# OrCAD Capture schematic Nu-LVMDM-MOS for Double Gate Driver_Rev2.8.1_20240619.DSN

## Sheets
1 Driver Board: size A3; title: Driver Board; rev: V1.0
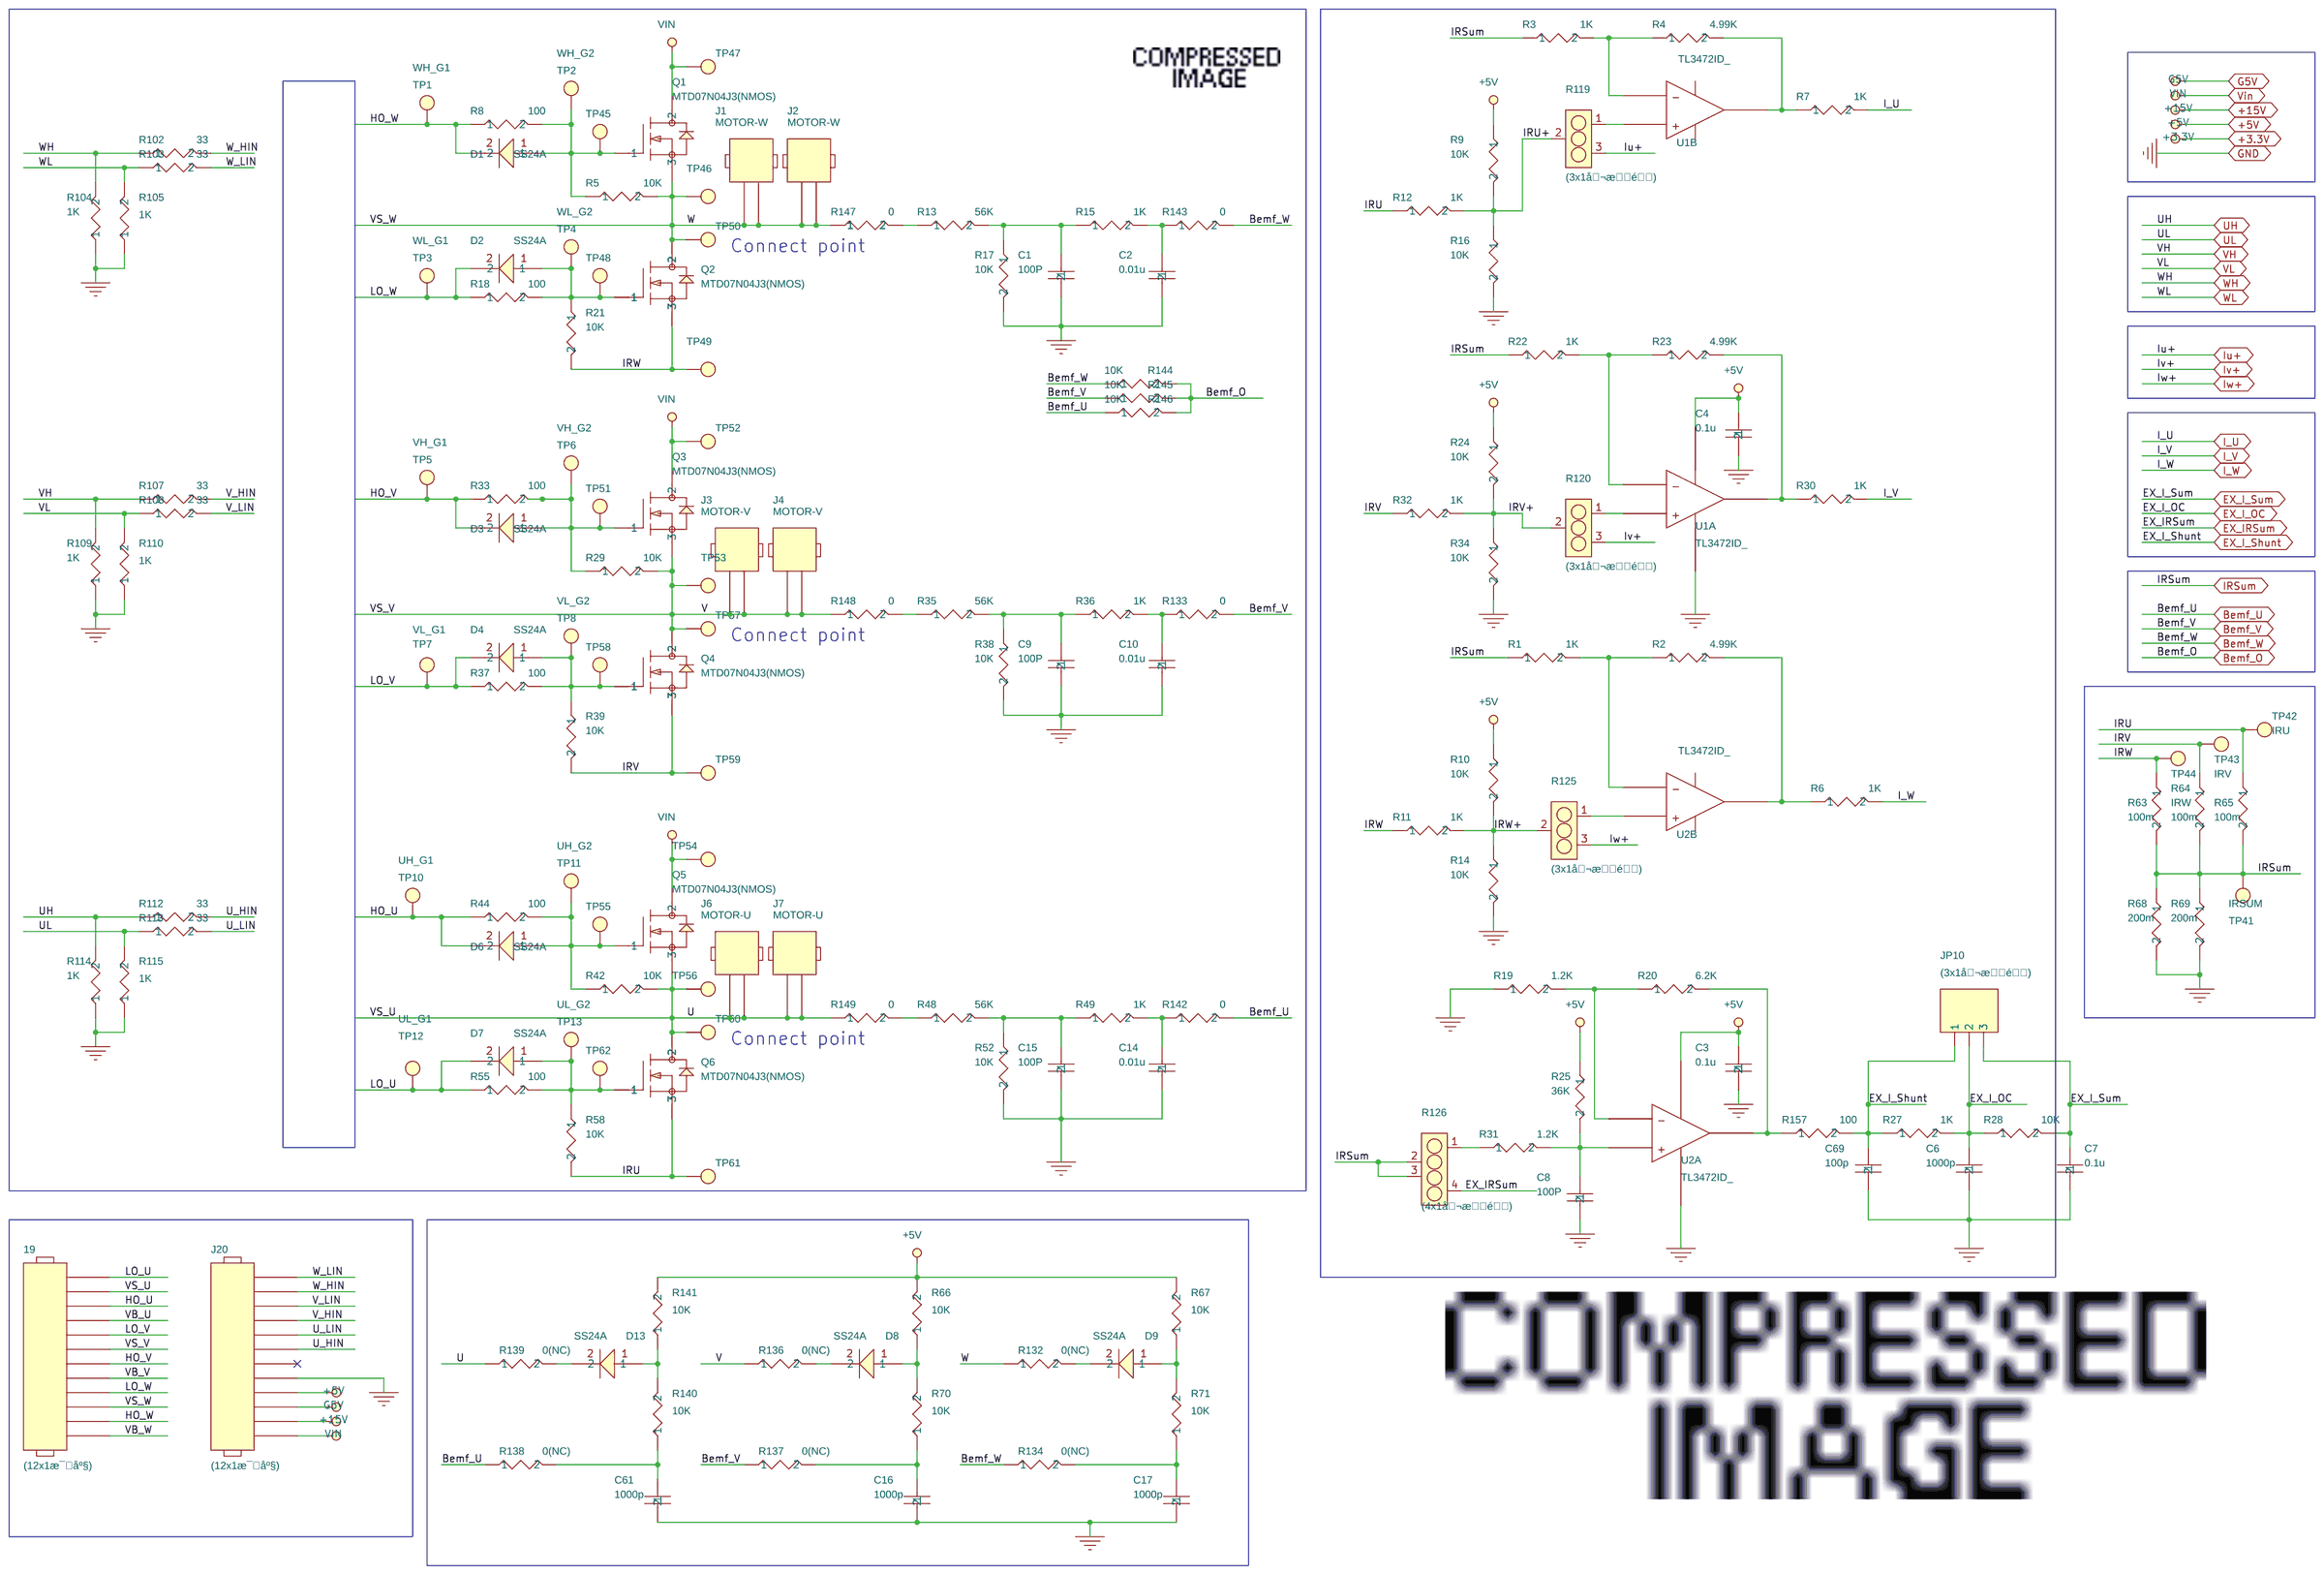
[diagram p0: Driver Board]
2 Power: size A4; title: Power; rev: 1.0
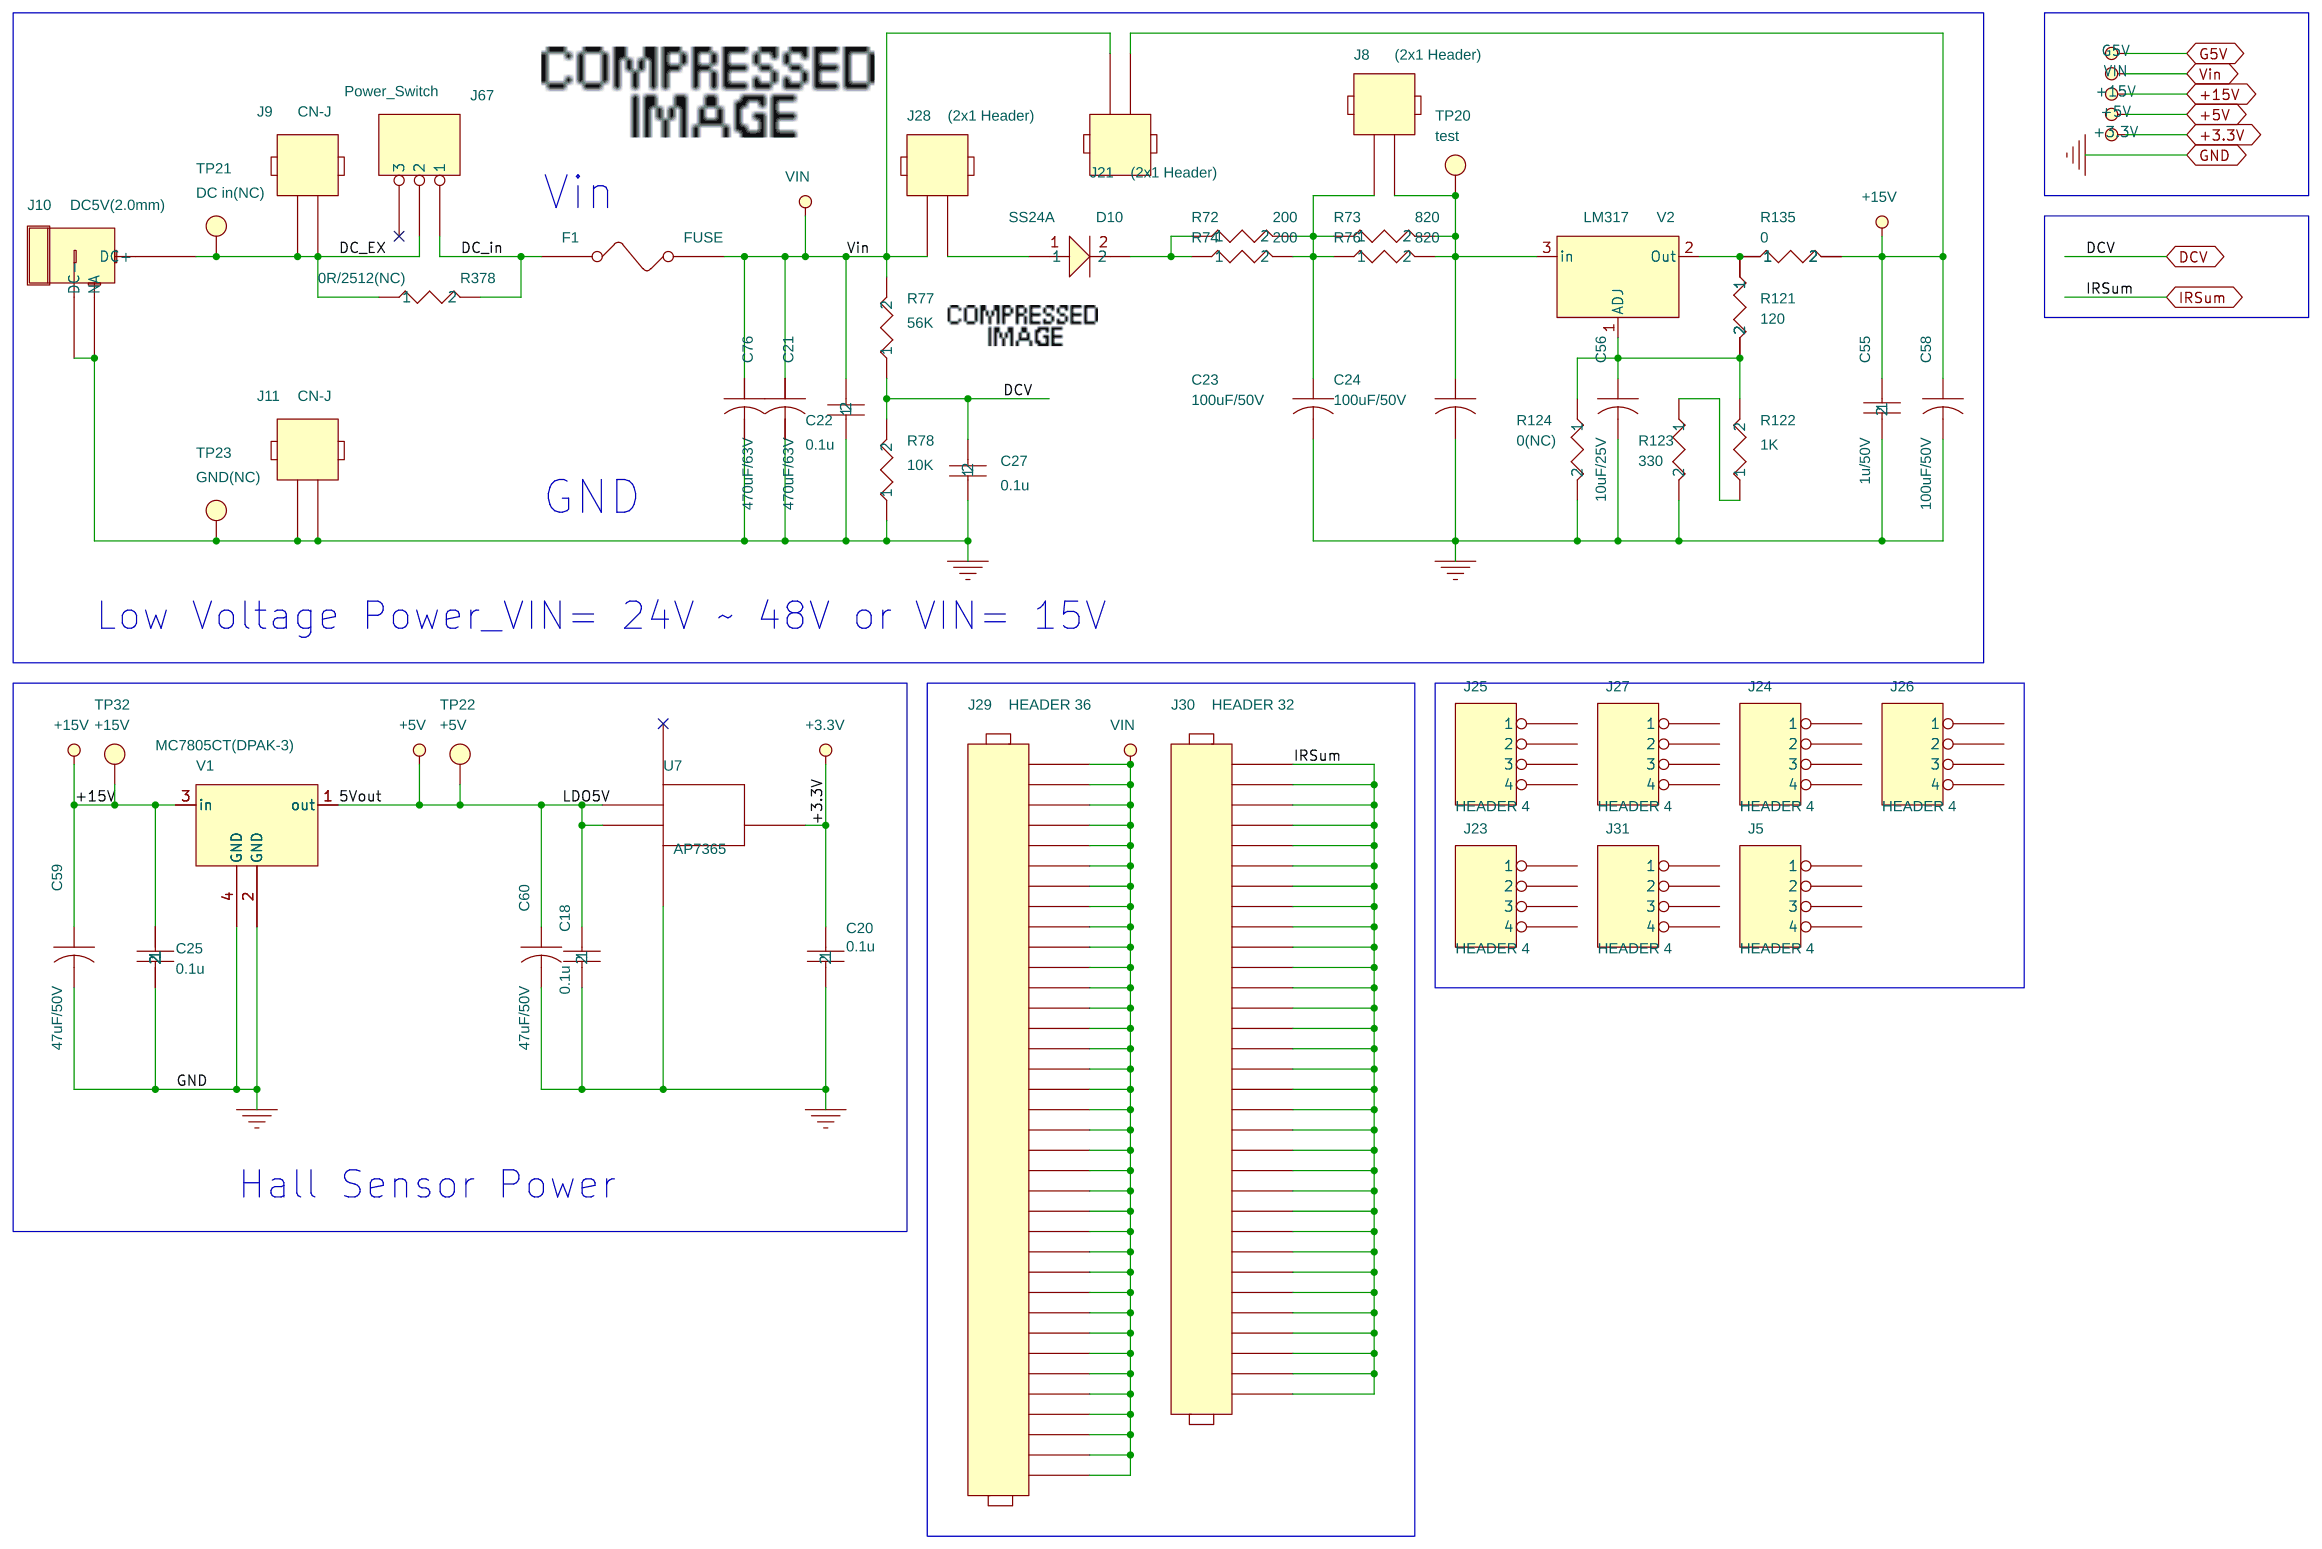
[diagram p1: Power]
3 Connect: size A4; title: Nu-LVMDM-MOS V2.8.1; rev: 1.0
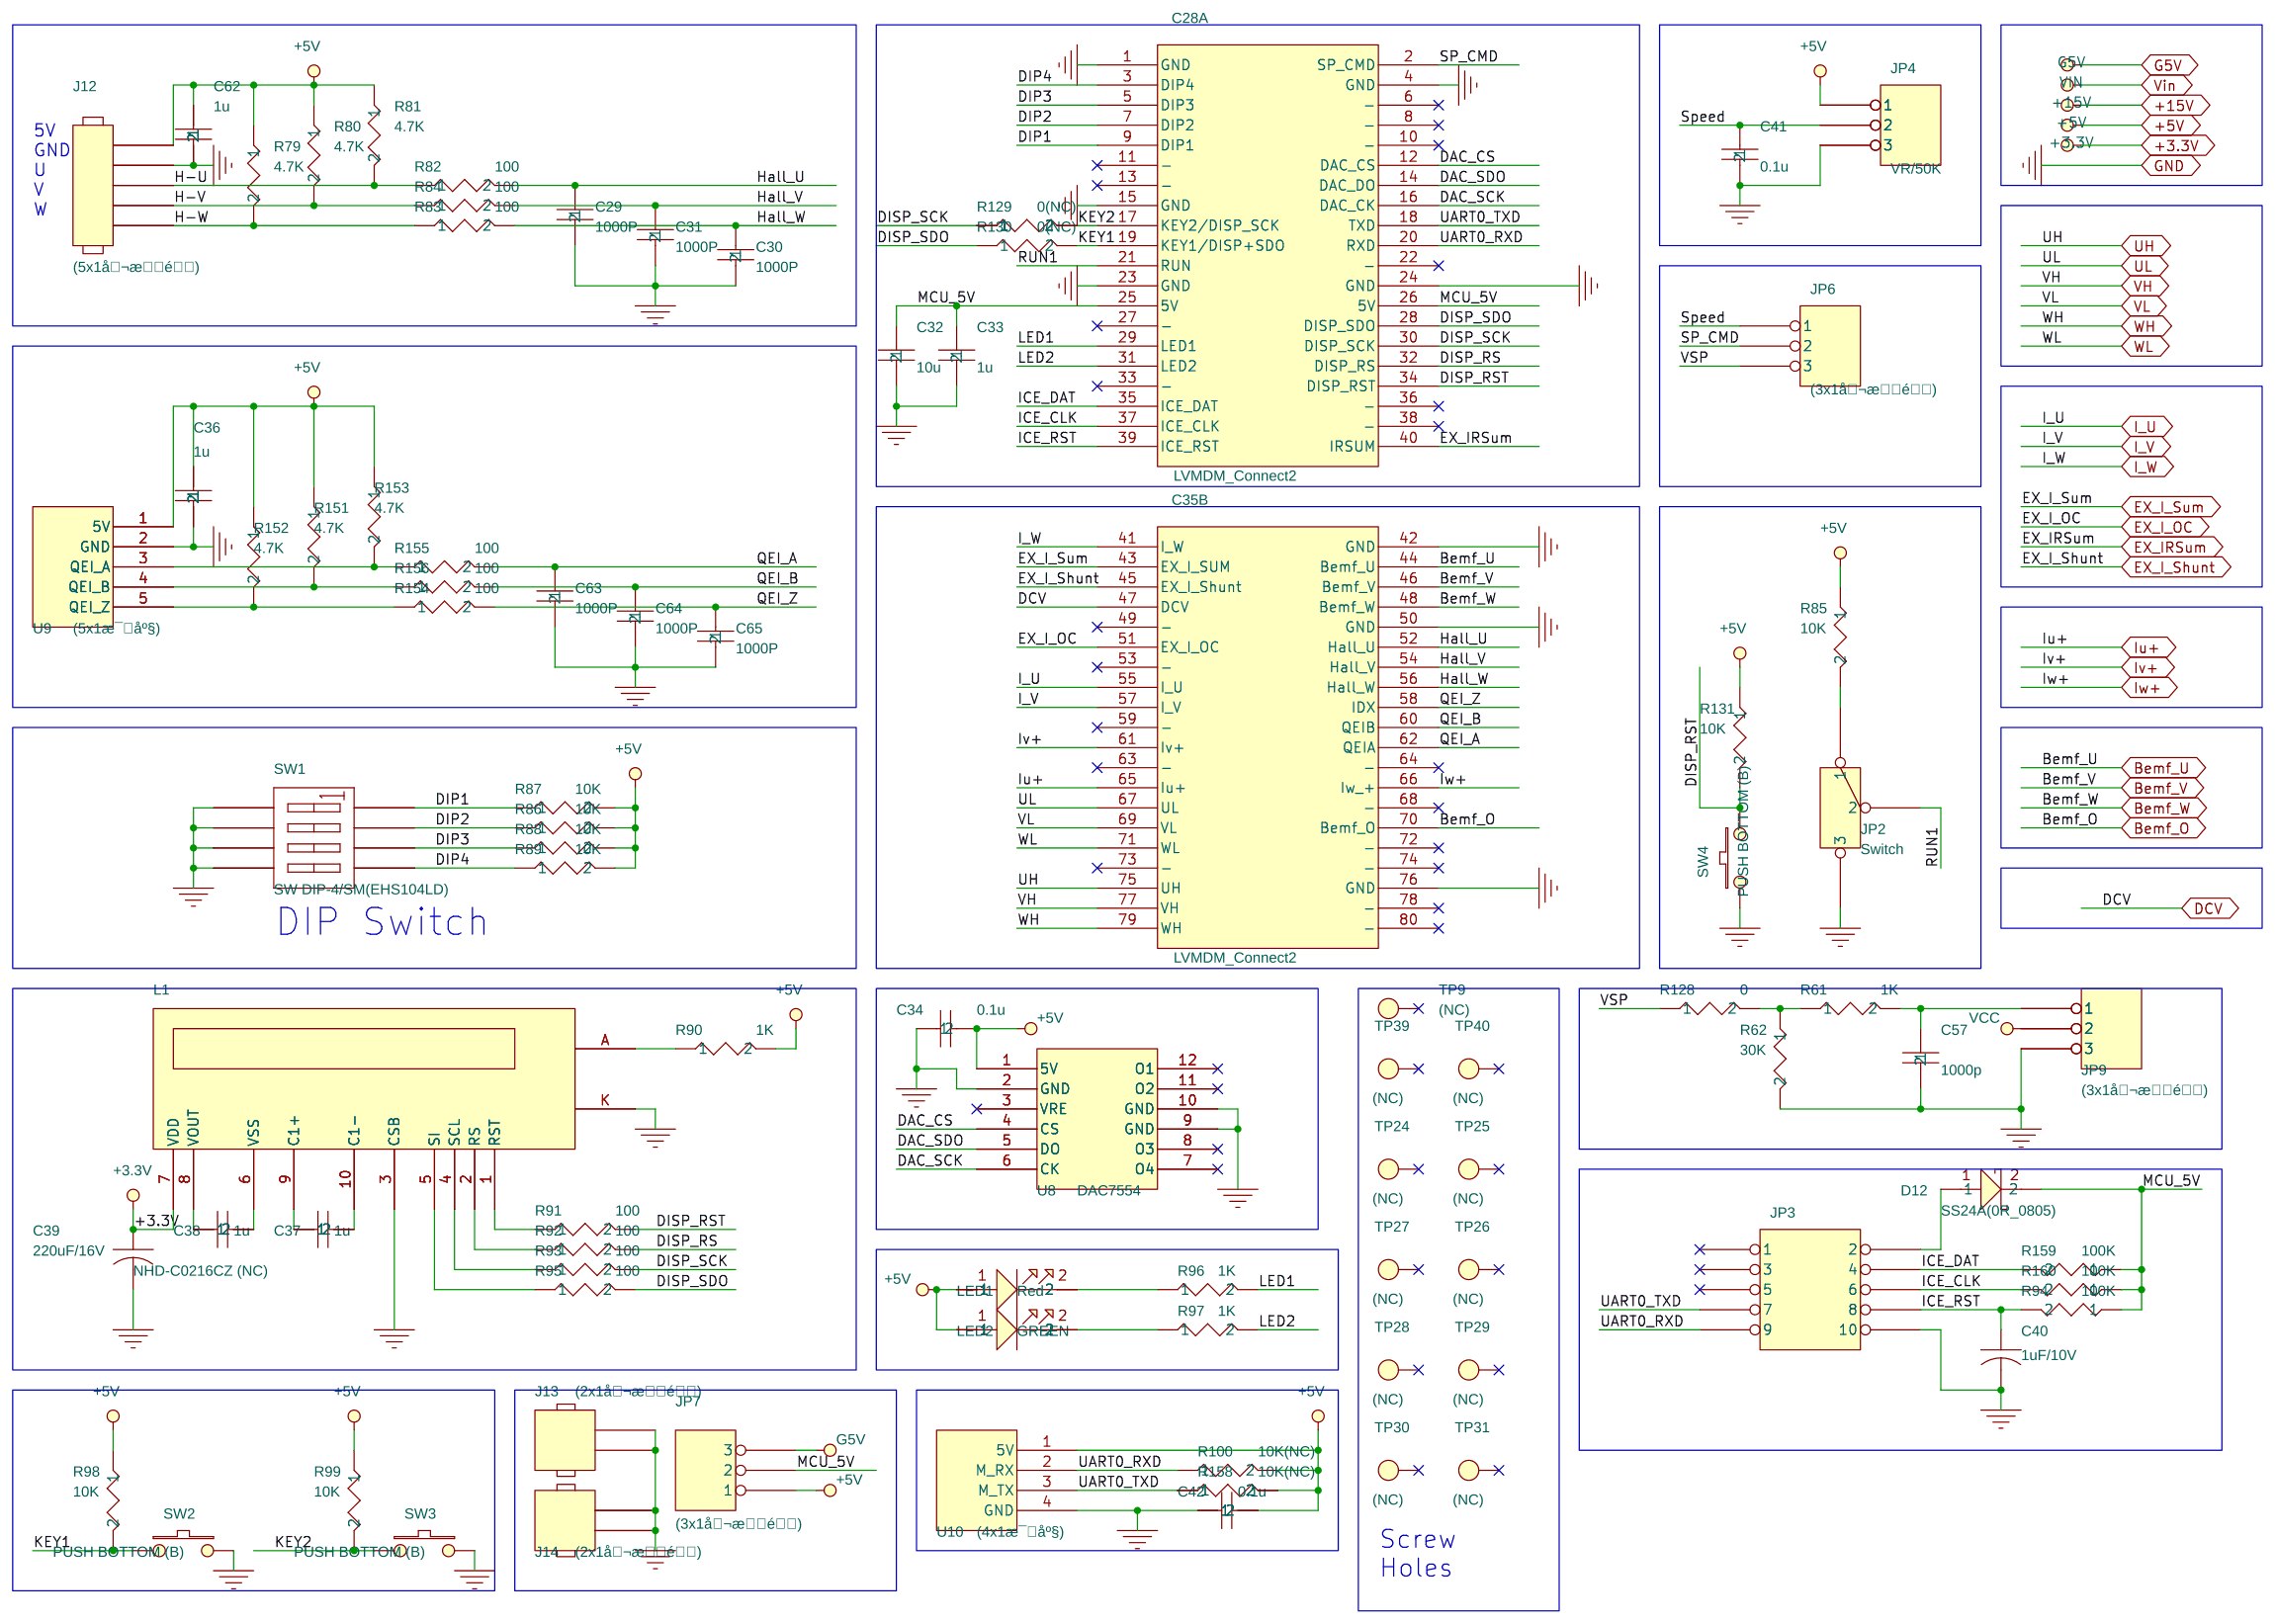
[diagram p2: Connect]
4 Nu-Link-ME V3.0: size A4; title: Nu-Link-Me; rev: 3.0; note: 1
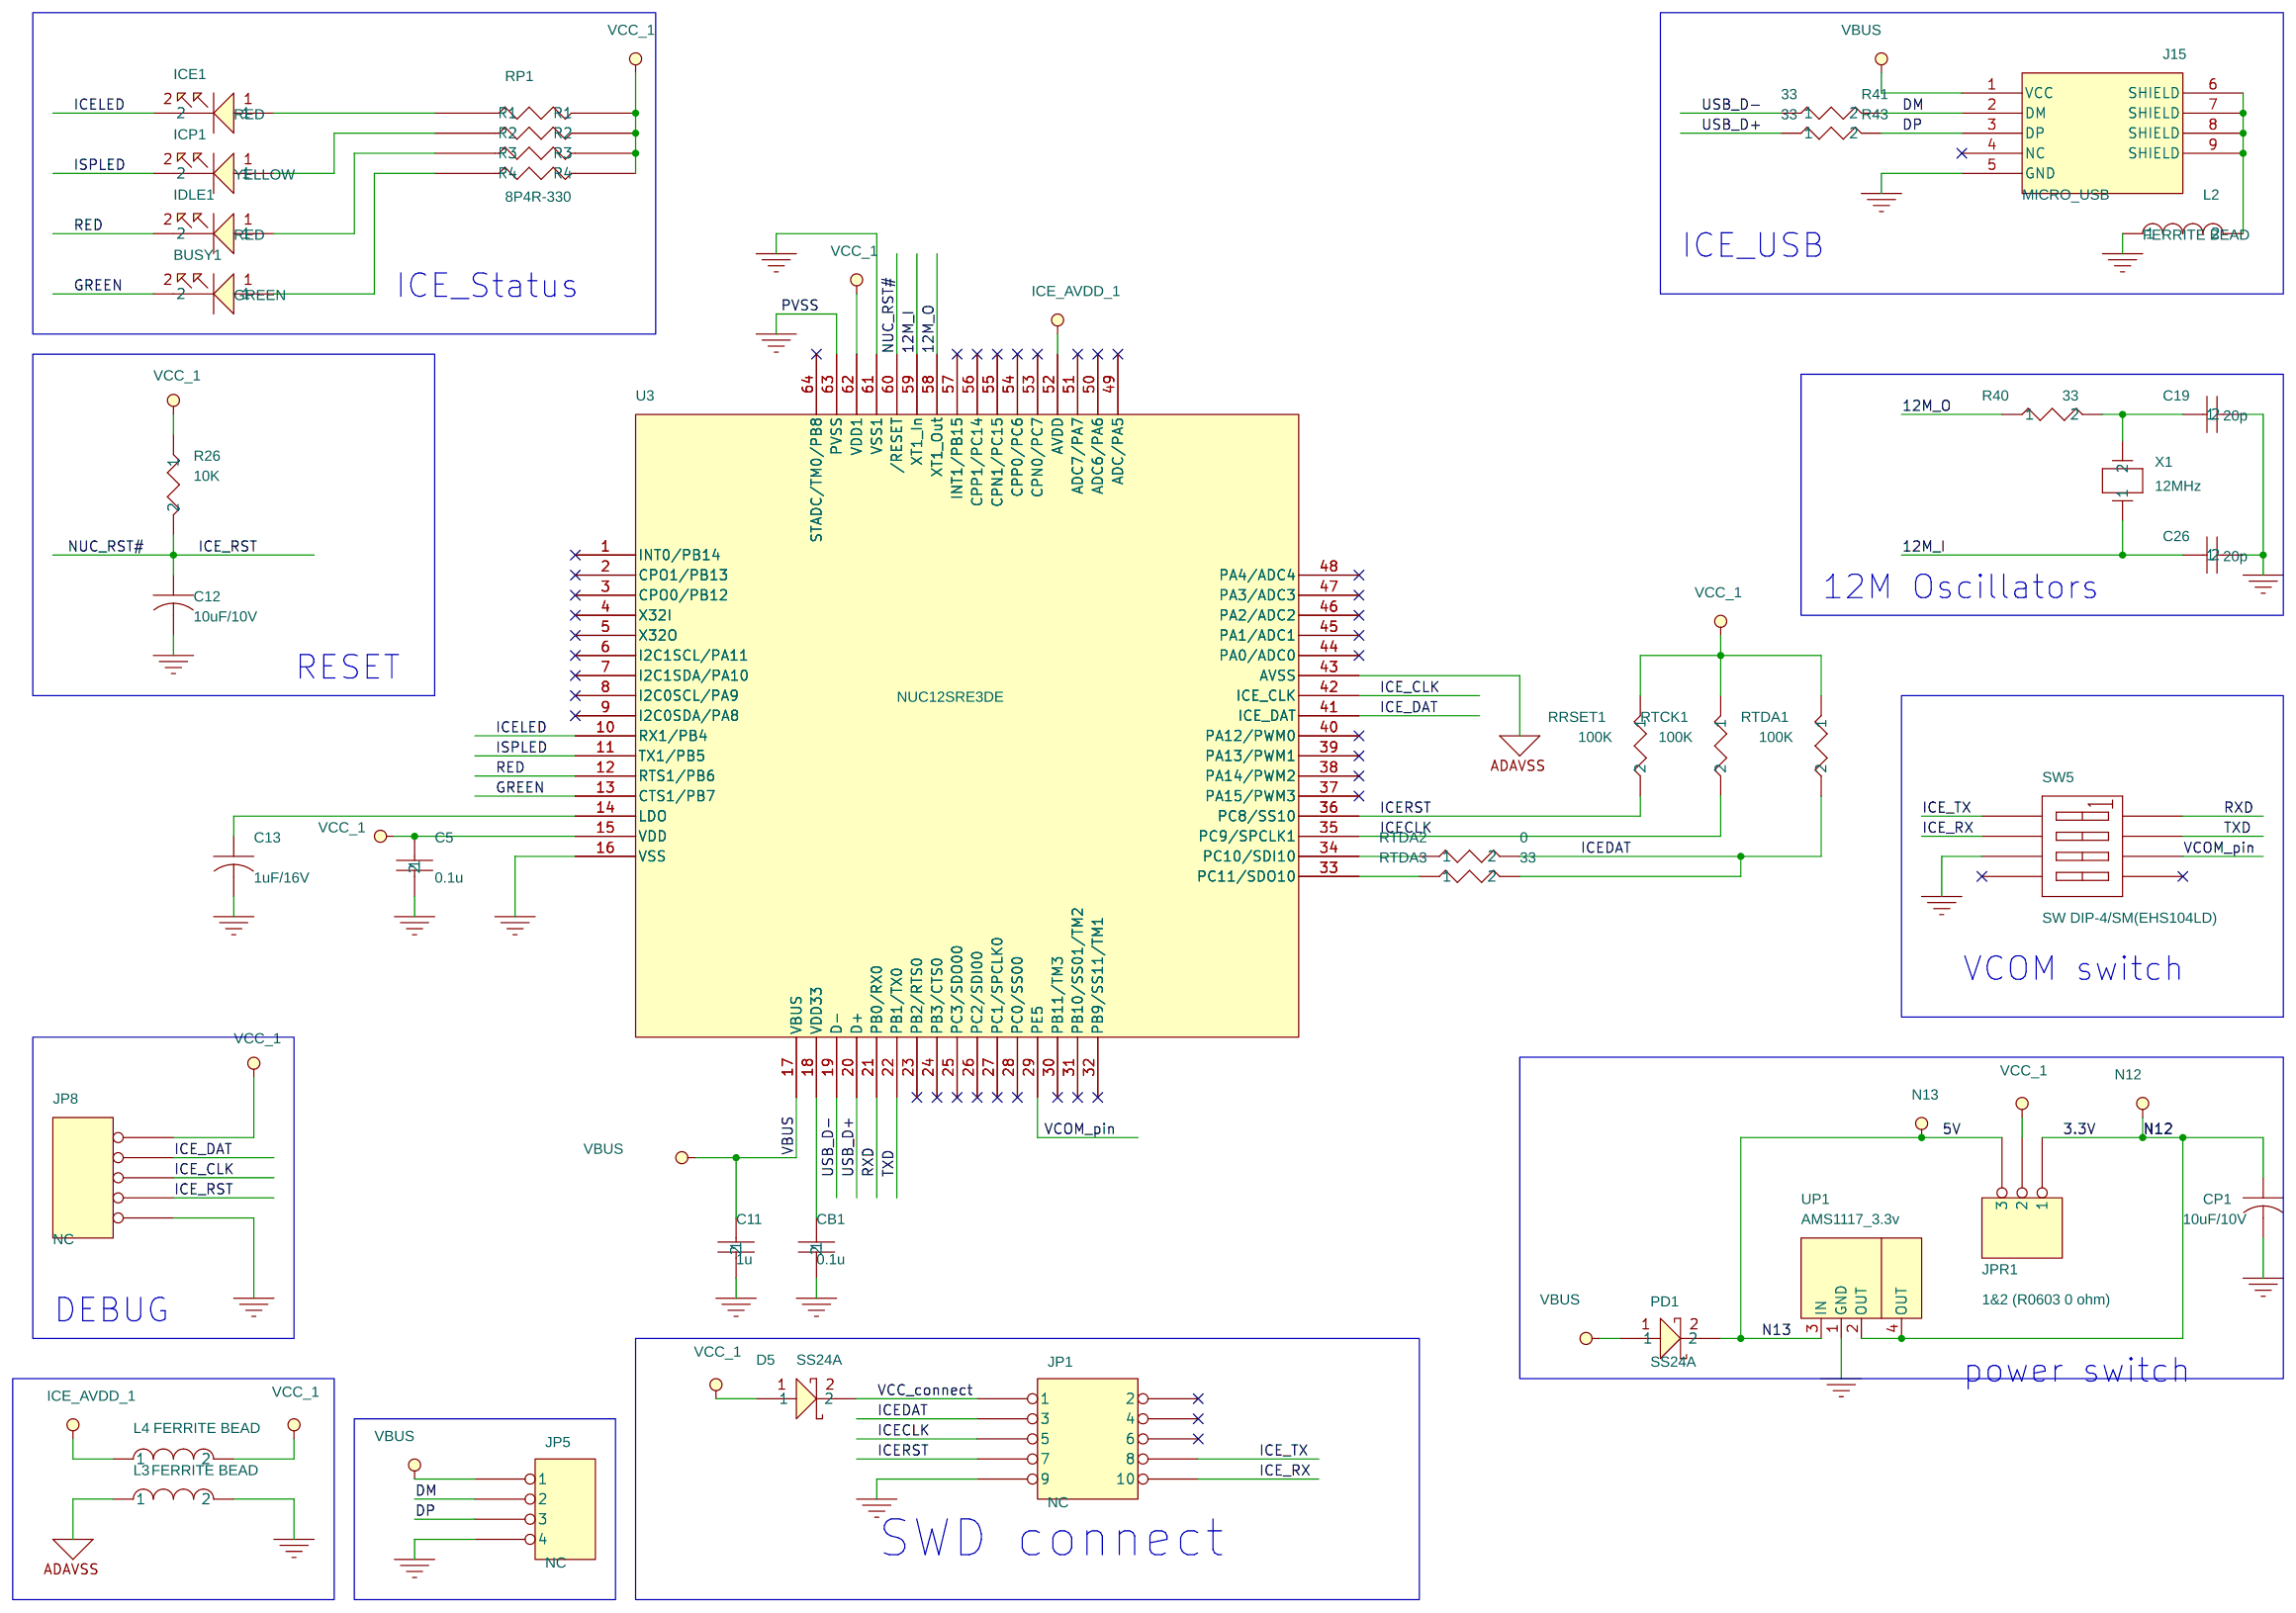
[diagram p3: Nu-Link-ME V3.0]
5 Nu-Link-ME V3.0 (2): size A4; title: Nu-Link-Me; rev: 3.0; note: 1
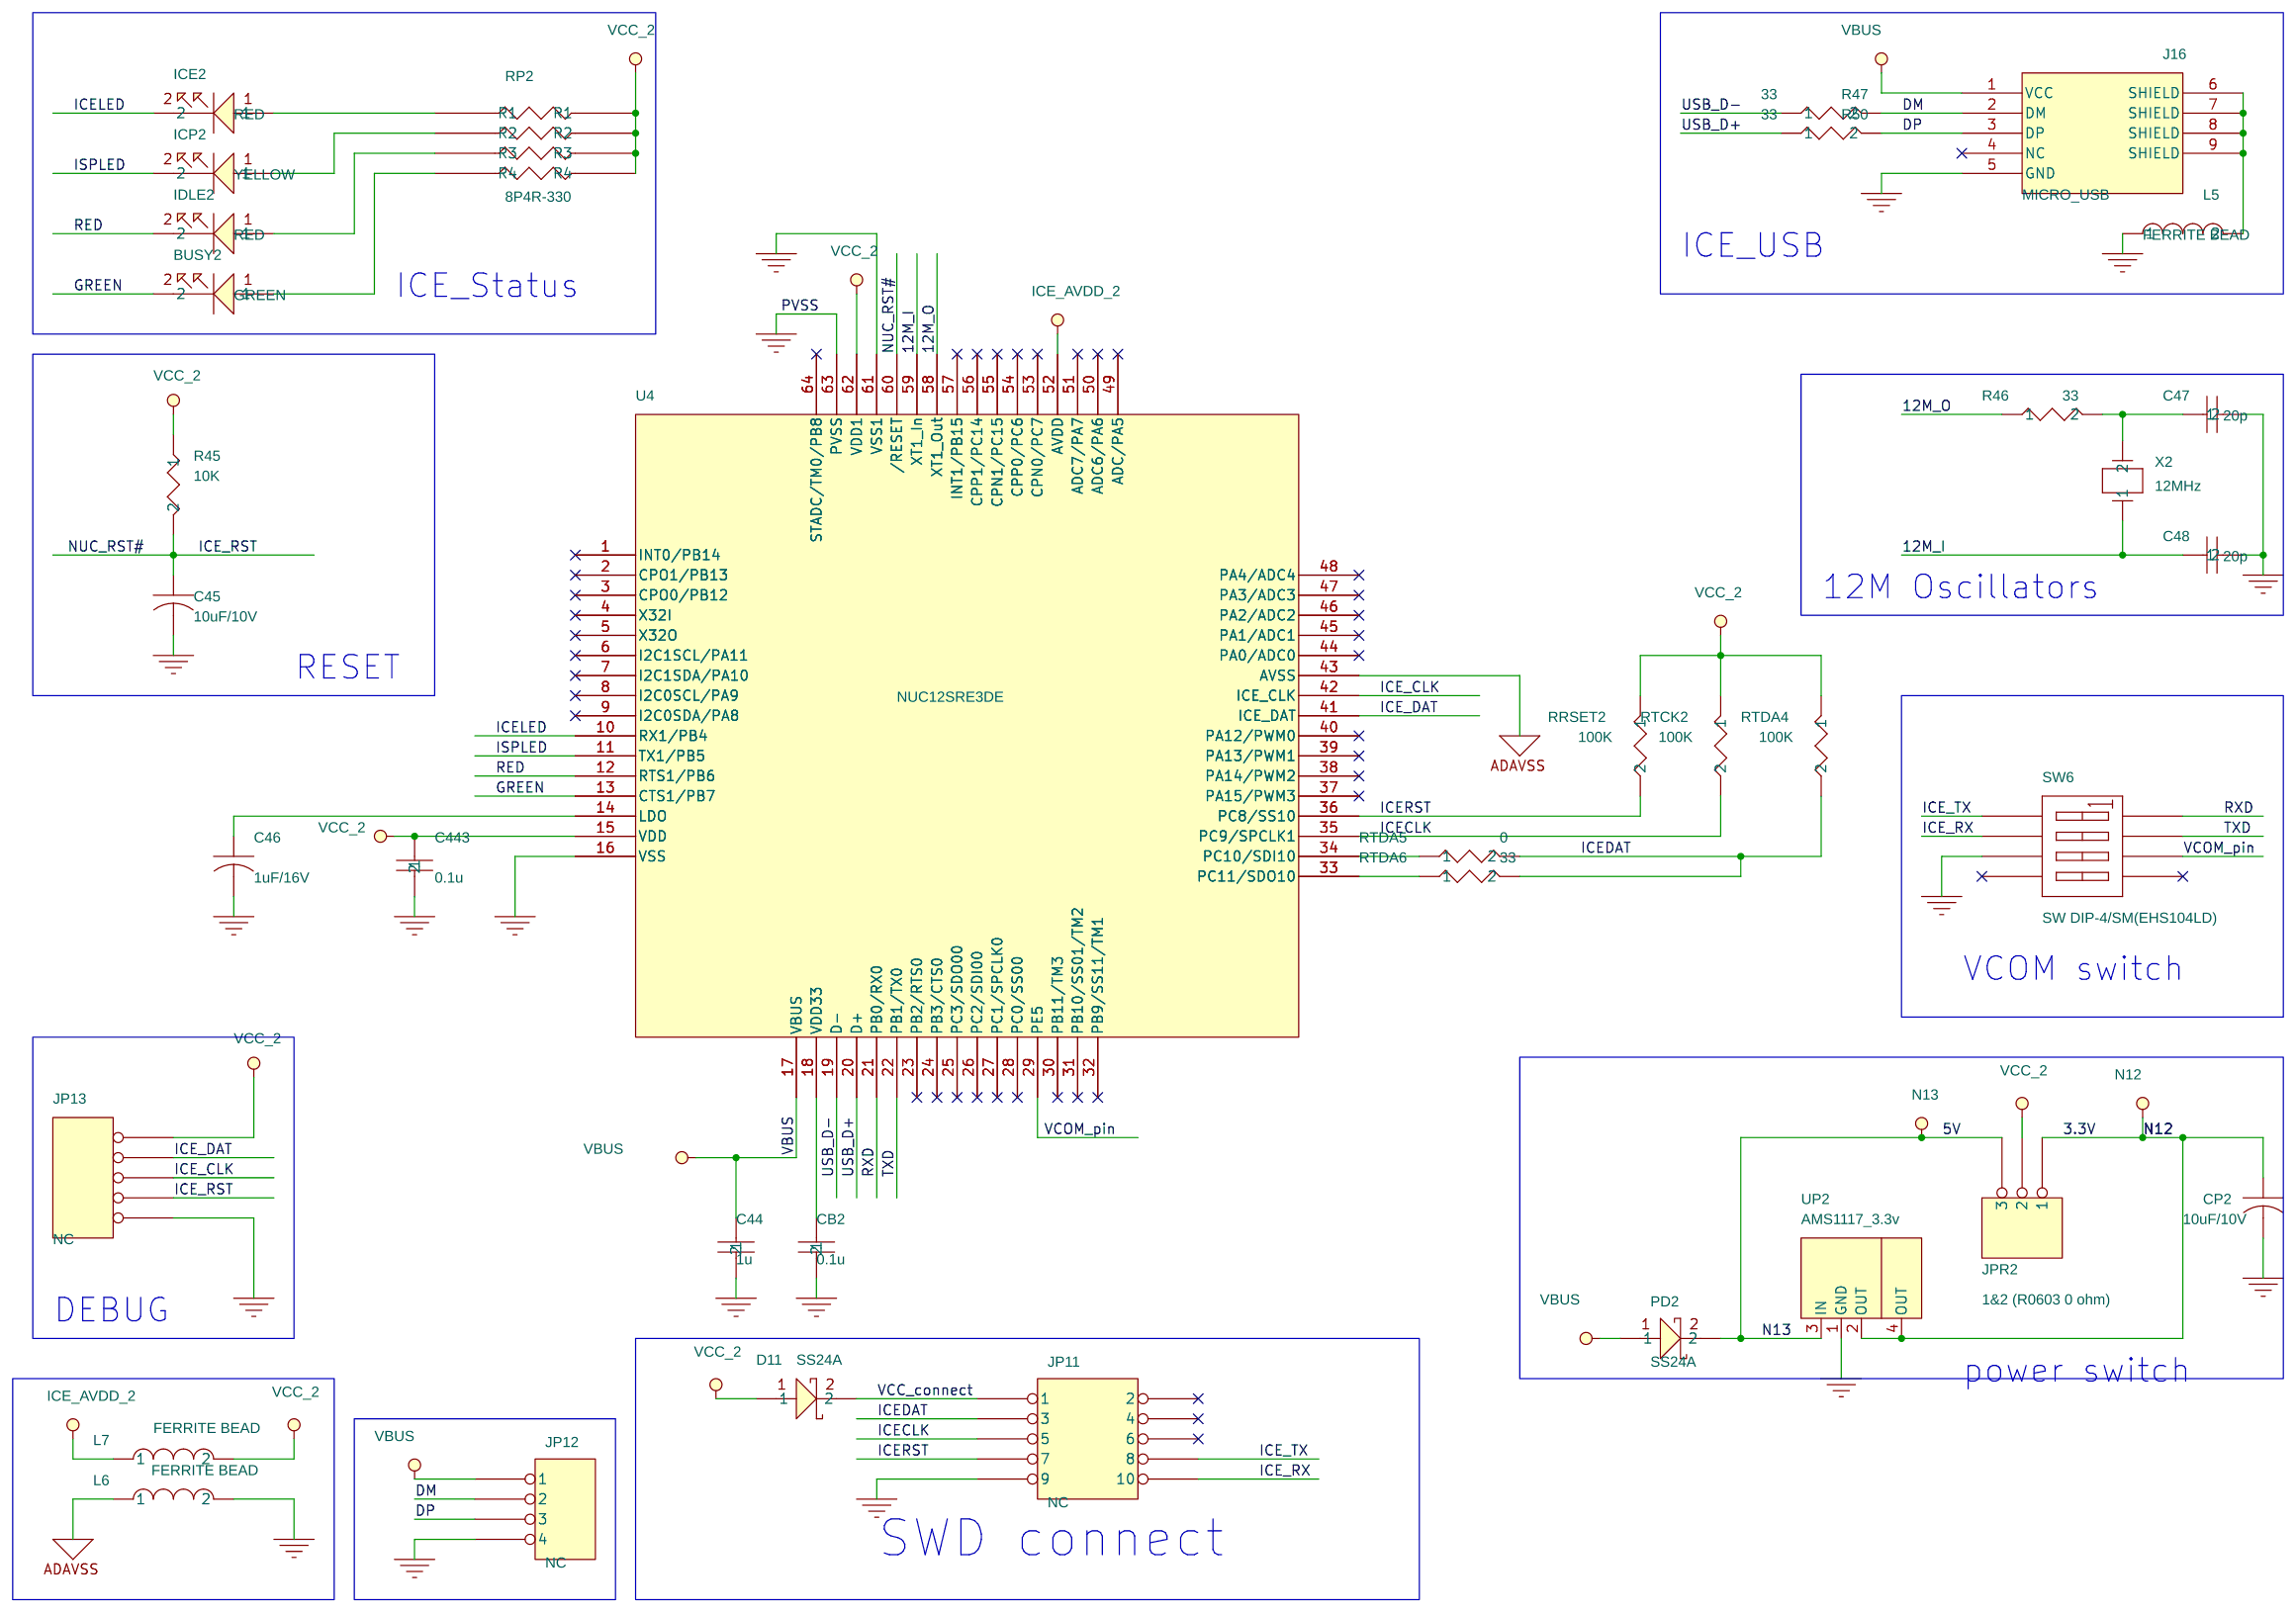
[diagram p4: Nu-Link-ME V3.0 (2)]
6 IR2101: size A4; title: IR1201 Gate Driver
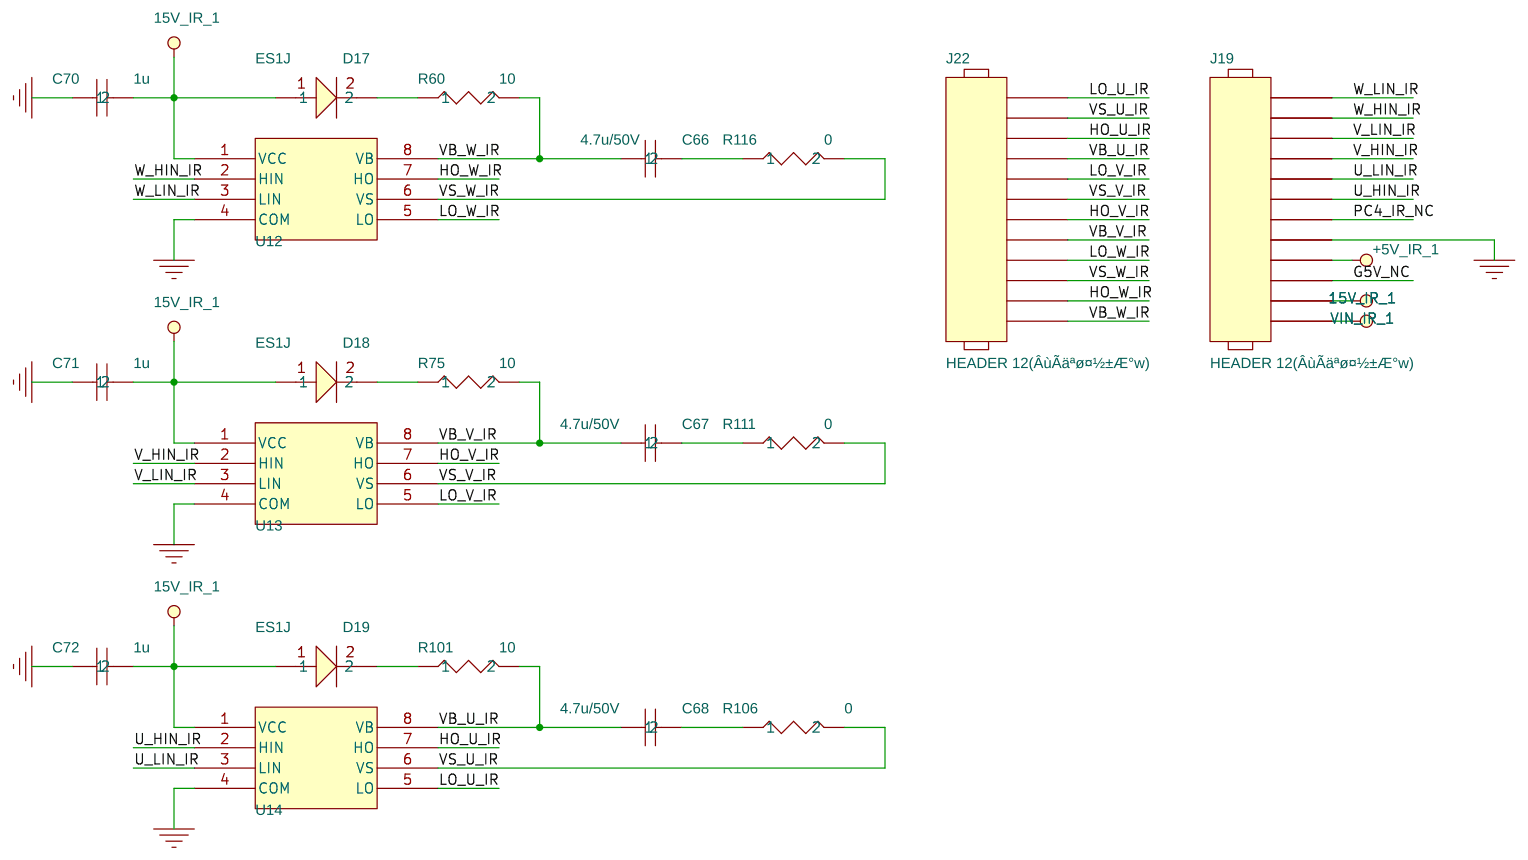
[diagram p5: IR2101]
7 IR2101 (2): size A4; title: IR1201 Gate Driver
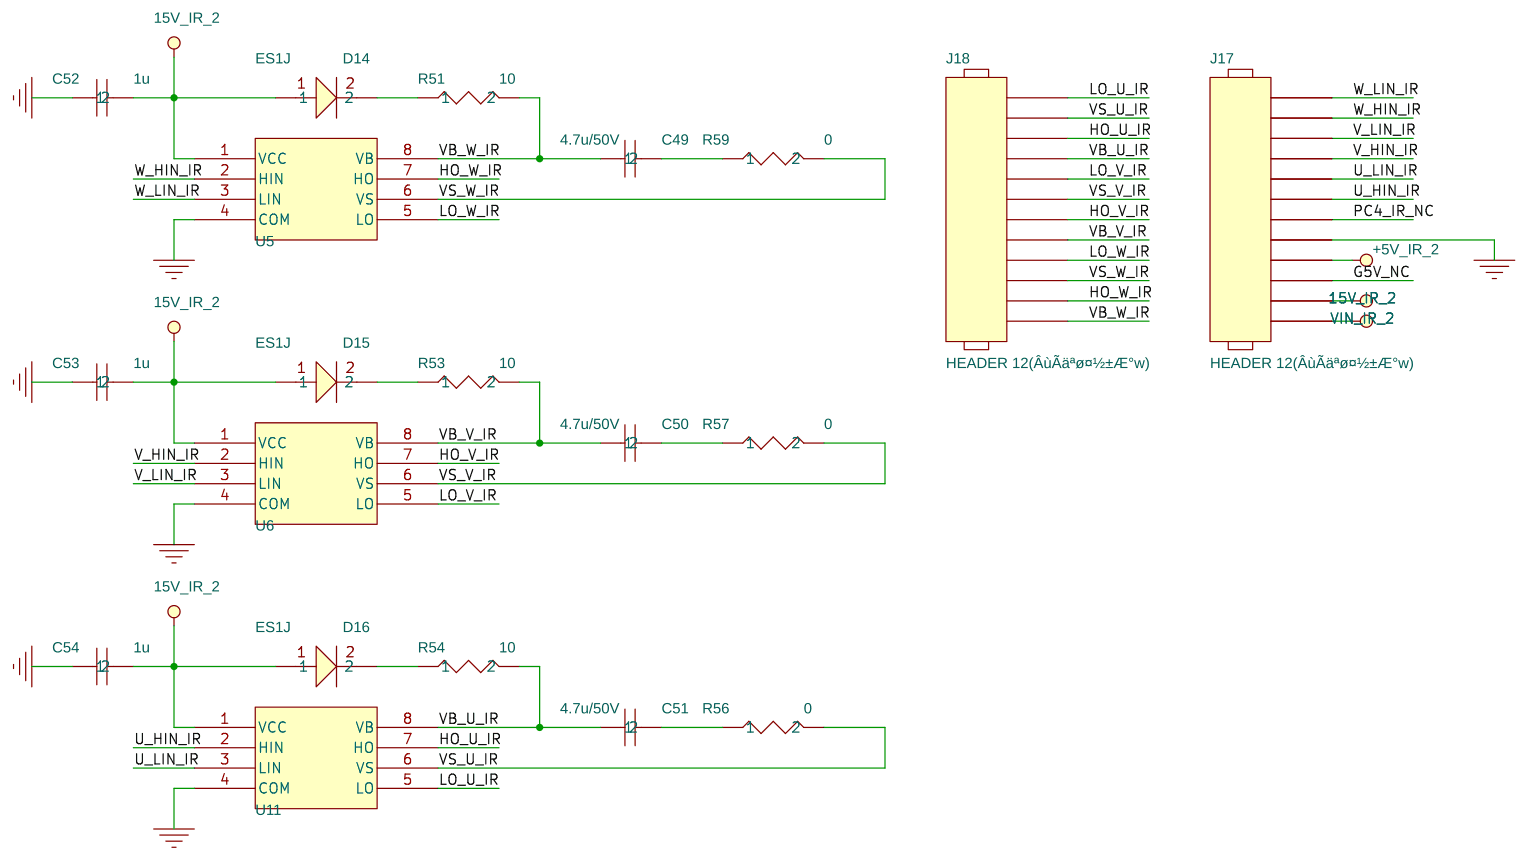
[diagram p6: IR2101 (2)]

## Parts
sheet Connect
C28  LVMDM_Connect2  [HEADER20X2]  (section A)
C29  1000P  [C0603]
C30  1000P  [C0603]
C31  1000P  [C0603]
C32  10u  [C0603]
C33  1u  [C0603]
C34  0.1u  [C0603]
C35  LVMDM_Connect2  [HEADER20X2]  (section B)
C36  1u  [C0603]
C37  1u  [C0603]
C38  1u  [C0603]
C39  220uF/16V  [ECAP6.3x5]
C40  1uF/10V  [TANT-A]
C41  0.1u  [C0603]
C42  0.1u  [C0603]
C57  1000p  [C0603]
C62  1u  [C0603]
C63  1000P  [C0603]
C64  1000P  [C0603]
C65  1000P  [C0603]
D12  SS24A(0R_0805)  [RB060L]
J12  (5x1å¬æé)  [HEADER1X5]
J13  (2x1å¬æé)  [Sip-2p]
J14  (2x1å¬æé)  [Sip-2p]
JP2  Switch  [DIP3]
JP3  HEADER 5X2  [Header2x5]
JP4  VR/50K  [VR-10X10.3]
JP6  (3x1å¬æé)  [HEADER3]
JP7  (3x1å¬æé)  [header3]
JP9  (3x1å¬æé)  [HEADER3]
L1  NHD-C0216CZ (NC)  [NHD-C0216CZ]
LED1  Red  [LED0805]
LED2  GREEN  [LED0805]
R61  1K  [R0603]
R62  30K  [R0603]
R79  4.7K  [R0603]
R80  4.7K  [R0603]
R81  4.7K  [R0603]
R82  100  [R0603]
R83  100  [R0603]
R84  100  [R0603]
R85  10K  [R0603]
R86  10K  [R0603]
R87  10K  [R0603]
R88  10K  [R0603]
R89  10K  [R0603]
R90  1K  [R0603]
R91  100  [R0603]
R92  100  [R0603]
R93  100  [R0603]
R94  100K  [R0603]
R95  100  [R0603]
R96  1K  [R0603]
R97  1K  [R0603]
R98  10K  [R0603]
R99  10K  [R0603]
R100  10K(NC)  [R0603]
R128  0  [R0603]
R129  0(NC)  [R0603]
R130  0(NC)  [R0603]
R131  10K  [R0603]
R151  4.7K  [R0603]
R152  4.7K  [R0603]
R153  4.7K  [R0603]
R154  100  [R0603]
R155  100  [R0603]
R156  100  [R0603]
R158  10K(NC)  [R0603]
R159  100K  [R0603]
R160  100K  [R0603]
SW1  SW DIP-4/SM(EHS104LD)  [DIP8]
SW2  PUSH BOTTOM (B)  [SW]
SW3  PUSH BOTTOM (B)  [SW]
SW4  PUSH BOTTOM (B)  [SW]
TP9  (NC)  [GND_H]
TP24  (NC)  [GND_H]
TP25  (NC)  [GND_H]
TP26  (NC)  [GND_H]
TP27  (NC)  [GND_H]
TP28  (NC)  [GND_H]
TP29  (NC)  [GND_H]
TP30  (NC)  [GND_H]
TP31  (NC)  [GND_H]
TP39  (NC)  [GND_H]
TP40  (NC)  [GND_H]
U8  NM1530VE3AE  [DAC7554]
U9  NM1530VE3AE  [Header1x5]
U10  NM1530VE3AE  [Header1x4]
sheet Driver Board
19  (12x1æ¯åº§)  [HEADER12x1]
C1  100P  [C0603]
C2  0.01u  [C0603]
C3  0.1u  [C0603]
C4  0.1u  [C0603]
C6  1000p  [C0603]
C7  0.1u  [C0603]
C8  100P  [C0603]
C9  100P  [C0603]
C10  0.01u  [C0603]
C14  0.01u  [C0603]
C15  100P  [C0603]
C16  1000p  [C0603]
C17  1000p  [C0603]
C61  1000p  [C0603]
C69  100p  [C0603]
D1  SS24A  [RB060L]
D2  SS24A  [RB060L]
D3  SS24A  [RB060L]
D4  SS24A  [RB060L]
D6  SS24A  [RB060L]
D7  SS24A  [RB060L]
D8  SS24A  [RB060L]
D9  SS24A  [RB060L]
D13  SS24A  [RB060L]
J1  MOTOR-W  [Sip-2p]
J2  MOTOR-W  [CN-J]
J3  MOTOR-V  [Sip-2p]
J4  MOTOR-V  [CN-J]
J6  MOTOR-U  [Sip-2p]
J7  MOTOR-U  [CN-J]
J20  (12x1æ¯åº§)  [HEADER12x1]
JP10  (3x1å¬æé)  [Header3]
Q1  MTD07N04J3(NMOS)  [MOS_RU3060L]
Q2  MTD07N04J3(NMOS)  [MOS_RU3060L]
Q3  MTD07N04J3(NMOS)  [MOS_RU3060L]
Q4  MTD07N04J3(NMOS)  [MOS_RU3060L]
Q5  MTD07N04J3(NMOS)  [MOS_RU3060L]
Q6  MTD07N04J3(NMOS)  [MOS_RU3060L]
R1  1K  [R0603]
R2  4.99K  [R0603]
R3  1K  [R0603]
R4  4.99K  [R0603]
R5  10K  [R0603]
R6  1K  [R0603]
R7  1K  [R0603]
R8  100  [R1206]
R9  10K  [R0603]
R10  10K  [R0603]
R11  1K  [R0603]
R12  1K  [R0603]
R13  56K  [R0603]
R14  10K  [R0603]
R15  1K  [R0603]
R16  10K  [R0603]
R17  10K  [R0603]
R18  100  [R1206]
R19  1.2K  [R0603]
R20  6.2K  [R0603]
R21  10K  [R0603]
R22  1K  [R0603]
R23  4.99K  [R0603]
R24  10K  [R0603]
R25  36K  [R0603]
R27  1K  [R0603]
R28  10K  [R0603]
R29  10K  [R0603]
R30  1K  [R0603]
R31  1.2K  [R0603]
R32  1K  [R0603]
R33  100  [R1206]
R34  10K  [R0603]
R35  56K  [R0603]
R36  1K  [R0603]
R37  100  [R1206]
R38  10K  [R0603]
R39  10K  [R0603]
R42  10K  [R0603]
R44  100  [R1206]
R48  56K  [R0603]
R49  1K  [R0603]
R52  10K  [R0603]
R55  100  [R1206]
R58  10K  [R0603]
R63  100m  [2512]
R64  100m  [2512]
R65  100m  [2512]
R66  10K  [R0603]
R67  10K  [R0603]
R68  200m  [2512]
R69  200m  [2512]
R70  10K  [R0603]
R71  10K  [R0603]
R102  33  [R0603]
R103  33  [R0603]
R104  1K  [R0603]
R105  1K  [R0603]
R107  33  [R0603]
R108  33  [R0603]
R109  1K  [R0603]
R110  1K  [R0603]
R112  33  [R0603]
R113  33  [R0603]
R114  1K  [R0603]
R115  1K  [R0603]
R119  (3x1å¬æé)  [HEADER3]
R120  (3x1å¬æé)  [HEADER3]
R125  (3x1å¬æé)  [HEADER3]
R126  (4x1å¬æé)  [Header1x4]
R132  0(NC)  [R0603]
R133  0  [R0603]
R134  0(NC)  [R0603]
R136  0(NC)  [R0603]
R137  0(NC)  [R0603]
R138  0(NC)  [R0603]
R139  0(NC)  [R0603]
R140  10K  [R0603]
R141  10K  [R0603]
R142  0  [R0603]
R143  0  [R0603]
R144  10K  [R0603]
R145  10K  [R0603]
R146  10K  [R0603]
R147  0  [R0603]
R148  0  [R0603]
R149  0  [R0603]
R157  100  [R0603]
TP1  WH_G1  [Header1]
TP2  WH_G2  [Header1]
TP3  WL_G1  [Header1]
TP4  WL_G2  [Header1]
TP5  VH_G1  [Header1]
TP6  VH_G2  [Header1]
TP7  VL_G1  [Header1]
TP8  VL_G2  [Header1]
TP10  UH_G1  [Header1]
TP11  UH_G2  [Header1]
TP12  UL_G1  [Header1]
TP13  UL_G2  [Header1]
TP41  IRSUM  [Header1]
TP42  IRU  [Header1]
TP43  IRV  [Header1]
TP44  IRW  [Header1]
TP45  NC  [Header1]
TP46  NC  [Header1]
TP47  NC  [Header1]
TP48  NC  [Header1]
TP49  NC  [Header1]
TP50  NC  [Header1]
TP51  NC  [Header1]
TP52  NC  [Header1]
TP53  NC  [Header1]
TP54  NC  [Header1]
TP55  NC  [Header1]
TP56  NC  [Header1]
TP57  NC  [Header1]
TP58  NC  [Header1]
TP59  NC  [Header1]
TP60  NC  [Header1]
TP61  NC  [Header1]
TP62  NC  [Header1]
U1  TL3472ID_  [SO-8]  (sections A,B)
U2  TL3472ID_  [SO-8]  (sections A,B)
sheet IR2101 (2)
C49  4.7u/50V  [C1206]
C50  4.7u/50V  [C1206]
C51  4.7u/50V  [C1206]
C52  1u  [C0805]
C53  1u  [C0805]
C54  1u  [C0805]
D14  ES1J  [RB060L]
D15  ES1J  [RB060L]
D16  ES1J  [RB060L]
J17  HEADER 12(ÂùÃäªø¤½±Æ°w)  [HEADER12x1]
J18  HEADER 12(ÂùÃäªø¤½±Æ°w)  [HEADER12x1]
R51  10  [R0603]
R53  10  [R0603]
R54  10  [R0603]
R56  0  [R0603]
R57  0  [R0603]
R59  0  [R0603]
U5  NM1530VE3AE  [SO-8]
U6  NM1530VE3AE  [SO-8]
U11  NM1530VE3AE  [SO-8]
sheet IR2101
C66  4.7u/50V  [C1206]
C67  4.7u/50V  [C1206]
C68  4.7u/50V  [C1206]
C70  1u  [C0805]
C71  1u  [C0805]
C72  1u  [C0805]
D17  ES1J  [RB060L]
D18  ES1J  [RB060L]
D19  ES1J  [RB060L]
J19  HEADER 12(ÂùÃäªø¤½±Æ°w)  [HEADER12x1]
J22  HEADER 12(ÂùÃäªø¤½±Æ°w)  [HEADER12x1]
R60  10  [R0603]
R75  10  [R0603]
R101  10  [R0603]
R106  0  [R0603]
R111  0  [R0603]
R116  0  [R0603]
U12  NM1530VE3AE  [SO-8]
U13  NM1530VE3AE  [SO-8]
U14  NM1530VE3AE  [SO-8]
sheet Nu-Link-ME V3.0 (2)
BUSY2  GREEN  [LED0805]
C44  1u  [C0603]
C45  10uF/10V  [TANT-A]
C46  1uF/16V  [TANT-A]
C47  20p  [C0603]
C48  20p  [C0603]
C443  0.1u  [C0603]
CB2  0.1u  [C0603]
CP2  10uF/10V  [TANT-A]
D11  SS24A  [RB060L]
ICE2  RED  [LED0805]
ICP2  YELLOW  [LED0805]
IDLE2  RED  [LED0805]
J16  MICRO_USB  [MICRO_USB_AB_LS]
JP11  NC  [HEADER5X2]
JP12  NC  [HEADER04]
JP13  NC  [HEADER05]
JPR2  1&2 (R0603 0 ohm)  [R0603X2]
L5  FERRITE BEAD  [L0603]
L6  FERRITE BEAD  [L0603]
L7  FERRITE BEAD  [L0603]
PD2  SS24A  [RB060L]
R45  10K  [R0603]
R46  33  [R0603]
R47  33  [R0603]
R50  33  [R0603]
RP2  8P4R-330  [8P4RA]
RRSET2  100K  [R0603]
RTCK2  100K  [R0603]
RTDA4  100K  [R0603]
RTDA5  0  [R0603]
RTDA6  33  [R0603]
SW6  SW DIP-4/SM(EHS104LD)  [SW1X4]
U4  NUC12SRE3DE  [NCU120_LQFP_64]
UP2  AMS1117_3.3v  [SOT-223-1]
X2  12MHz  [XTAL\LP\SMD]
sheet Nu-Link-ME V3.0
BUSY1  GREEN  [LED0805]
C5  0.1u  [C0603]
C11  1u  [C0603]
C12  10uF/10V  [TANT-A]
C13  1uF/16V  [TANT-A]
C19  20p  [C0603]
C26  20p  [C0603]
CB1  0.1u  [C0603]
CP1  10uF/10V  [TANT-A]
D5  SS24A  [RB060L]
ICE1  RED  [LED0805]
ICP1  YELLOW  [LED0805]
IDLE1  RED  [LED0805]
J15  MICRO_USB  [MICRO_USB_AB_LS]
JP1  NC  [HEADER5X2]
JP5  NC  [HEADER04]
JP8  NC  [HEADER05]
JPR1  1&2 (R0603 0 ohm)  [R0603X2]
L2  FERRITE BEAD  [L0603]
L3  FERRITE BEAD  [L0603]
L4  FERRITE BEAD  [L0603]
PD1  SS24A  [RB060L]
R26  10K  [R0603]
R40  33  [R0603]
R41  33  [R0603]
R43  33  [R0603]
RP1  8P4R-330  [8P4RA]
RRSET1  100K  [R0603]
RTCK1  100K  [R0603]
RTDA1  100K  [R0603]
RTDA2  0  [R0603]
RTDA3  33  [R0603]
SW5  SW DIP-4/SM(EHS104LD)  [SW1X4]
U3  NUC12SRE3DE  [NCU120_LQFP_64]
UP1  AMS1117_3.3v  [SOT-223-1]
X1  12MHz  [XTAL\LP\SMD]
sheet Power
C18  0.1u  [C0603]
C20  0.1u  [C0603]
C21  470uF/63V  [C_13.4_5MM]
C22  0.1u  [C0603]
C23  100uF/50V  [CAP_8_0.5]
C24  100uF/50V  [CAP_8_0.5]
C25  0.1u  [C0603]
C27  0.1u  [C0603]
C55  1u/50V  [C0805]
C56  10uF/25V  [CAP_5_0.5]
C58  100uF/50V  [CAP_8_0.5]
C59  47uF/50V  [CAP_6_0.5]
C60  47uF/50V  [CAP_6_0.5]
C76  470uF/63V  [C_13.4_5MM]
D10  SS24A  [RB060L]
F1  FUSE  [Fuse_S6125]
J5  HEADER 4  [HOLD4\2.0]
J8  (2x1 Header)  [Sip-2p]
J9  CN-J  [CN-J]
J10  DC5V(2.0mm)  [POWER-JACK-1]
J11  CN-J  [CN-J]
J21  (2x1 Header)  [Sip-2p]
J23  HEADER 4  [HOLD4\2.0]
J24  HEADER 4  [HOLD4\2.0]
J25  HEADER 4  [HOLD4\2.0]
J26  HEADER 4  [HOLD4\2.0]
J27  HEADER 4  [HOLD4\2.0]
J28  (2x1 Header)  [Sip-2p]
J29  HEADER 36  [PAD_UP]
J30  HEADER 32  [PAD_DOWN]
J31  HEADER 4  [HOLD4\2.0]
J67  Power_Switch  [Power_Switch]
R72  200  [DIP_R]
R73  820  [DIP_R]
R74  200  [DIP_R]
R76  820  [DIP_R]
R77  56K  [R0603]
R78  10K  [R0603]
R121  120  [R0603]
R122  1K  [R0603]
R123  330  [R0603]
R124  0(NC)  [R0603]
R135  0  [R1206]
R378  0R/2512(NC)  [2512]
TP20  test  [SIP\1P]
TP21  DC in(NC)  [Power_Via]
TP22  +5V  [SIP\1P]
TP23  GND(NC)  [Power_Via]
TP32  +15V  [SIP\1P]
U7  AP7365  [SOT-23-5]
V1  MC7805CT(DPAK-3)  [SOT-89-L]
V2  LM317  [HEADER3_LDO]

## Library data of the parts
C28 = LVMDM_Connect2_3
C29 = C_0.1u_15
C2 C30 = C_0.1u_6
C1 C25 C31 C54 C71 CB1 CB2 = C_0.1u
C17 C32 = C_0.1u_12
C33 C69 = C_0.1u_10
C6 C34 = C_0.1u_13
C35 = LVMDM_Connect2_5
C36 C51 C55 C61 C67 = C_0.1u_3
C14 C37 = C_0.1u_9
C3 C5 C27 C38 C52 C68 C443 = C_0.1u_1
C12 C21 C23 C24 C39 C40 C45 C56 C58-C60 C76 CP1 CP2 = C_10uF_10V
C15 C20 C41 C49 C72 = C_0.1u_4
C4 C42 = C_0.1u_7
C7 C57 = C_0.1u_11
C9 C18 C50 C62 C70 = C_0.1u_5
C16 C63 = C_0.1u_14
C8 C22 C53 C64 C66 = C_0.1u_2
C10 C65 = C_0.1u_8
D5 D11 D12 = D_SS24A
J12 = HEADER_5_v2
J1-J4 J6-J9 J11 J13 J14 J21 J28 = HEADER_2
JP2 = HEADER_3_0
JP1 JP3 JP11 = HEADER_5X2
JP4 = HEADER_3_3
JP6 = HEADER_3_2
J67 JP7 JPR1 JPR2 = HEADER_3
JP9 JP10 = HEADER_3_1
L1 = NHD-C0216CZ
BUSY1 BUSY2 LED1 = LED_GREEN
LED2 = LED_GREEN_1
R61 R103 = R_33_13
R38 R62 = R_10K_11
R79 = R_4.7K_4
R80 R135 = R_4.7K_3
R81 = R_4.7K_5
R33 R41 R47 R51 R82 R106 = R_33_3
R31 R83 = R_33_14
R55 R84 = R_33_8
R58 R85 = R_10K_1
R10 R86 = R_10K_3
R64 R87 = R_10K_9
R65 R88 = R_10K_5
R89 R146 = R_10K_13
R20 R90 = R_33_9
R48 R91 = R_33_12
R32 R40 R46 R59 R77 R92 R101 = R_33_1
R4 R93 = R_33_6
R70 R94 = R_10K_7
R8 R57 R95 R116 R122 RTDA3 RTDA6 = R_33
R43 R50 R54 R60 R96 R142 = R_33_2
R97 R138 = R_33_10
R67 R98 = R_10K_2
R99 R141 = R_10K_4
R26 R45 R63 R78 R100 = R_10K
R56 R75 R128 R143 = R_33_4
R28 R129 = R_10K_12
R14 R130 = R_10K_14
R69 R131 = R_10K_15
R124 R151 = R_4.7K
R121 R152 = R_4.7K_1
R123 R153 = R_4.7K_2
R53 R102 R111 R154 = R_33_5
R112 R155 = R_33_7
R13 R156 = R_33_11
R145 R158 = R_10K_6
R34 R159 = R_10K_8
R25 R160 = R_10K_10
SW1 SW5 SW6 = SW_DIP-4_SM
SW2 = PUSH_BOTTOM_(B)_1
SW3 = PUSH_BOTTOM_(B)
SW4 = PUSH_BOTTOM_(B)_2
TP1-TP13 TP20-TP32 TP39-TP62 = T_POINT_R
U8 = NM1530VE3AE_1
U9 = NM1530VE3AE_2: NM1530VE3AE: (5x1æ¯åº§)
U10 = NM1530VE3AE_3: NM1530VE3AE: (4x1æ¯åº§)
19 J17-J20 J22 = HEADER_12
D1 D16 D19 = D_SS24A_5_1
D2 = D_SS24A_5_3
D3 D10 D14 D17 = D_SS24A_5
D4 D15 D18 = D_SS24A_5_2
D6 = D_SS24A_5_4
D7 = D_SS24A_5_5
D8 = D_SS24A_9_1
D9 = D_SS24A_9
D13 = D_SS24A_9_2
Q1 = RU3060L_4
Q2 = RU3060L_3
Q3 = RU3060L_1
Q4 = RU3060L_5
Q5 = RU3060L
Q6 = RU3060L_2
R1 = R_33_43
R2 = R_33_34
R3 = R_33_51
R5 = R_10K_30
R6 = R_33_27
R7 = R_33_44
R9 = R_10K_16
R11 = R_33_20
R12 = R_33_30
R15 = R_33_22
R16 = R_10K_20
R17 = R_10K_28
R18 = R_33_45
R19 = R_33_25
R21 = R_10K_21
R22 = R_33_40
R23 = R_33_24
R24 = R_10K_27
R27 = R_33_28
R29 = R_10K_25
R30 = R_33_18
R35 = R_33_23
R36 = R_33_15
R37 = R_33_50
R39 = R_10K_24
R42 = R_10K_22
R44 = R_33_48
R49 = R_33_35
R52 = R_10K_18
R66 = R_10K_23
R68 = R_10K_19
R71 = R_10K_17
R104 = R_33_47
R105 = R_33_49
R107 = R_33_39
R108 = R_33_36
R109 = R_33_38
R110 = R_33_42
R113 = R_33_16
R114 = R_33_29
R115 = R_33_32
R119 R120 R125 = R0603X2_5
R126 = R0603X2_7
R132 = R_33_33
R133 = R_33_52
R134 = R_33_21
R136 = R_33_41
R137 = R_33_46
R139 = R_33_17
R140 = R_10K_26
R144 = R_10K_29
R147 = R_33_19
R148 = R_33_26
R149 = R_33_31
R157 = R_33_37
U1 U2 = TL3472ID_2
U5 U6 U11-U14 = NM1530VE3AE_0
C11 C44 = C_1u
C13 C46 = C_1uF_16V
C26 C47 = C_20p
C19 C48 = C_20p_1
ICE2 IDLE1 = LED_RED
ICP1 ICP2 = LED_YELLOW
ICE1 IDLE2 = LED_RED_1
J15 J16 = mini_USB_5pin
J25 JP5 JP12 = HEADER_4
JP8 JP13 = HEADER_5
L2 L5 = FERRITE_BEAD_2
L3 L6 = FERRITE_BEAD
L4 L7 = FERRITE_BEAD_1
PD1 PD2 = D_SS24A_1
RP1 RP2 = 8P4R-330
RRSET2 RTCK1 = R_100K_2
RTCK2 RTDA1 = R_100K
RRSET1 RTDA4 = R_100K_1
R378 RTDA2 RTDA5 = R_0
U3 U4 = NCU120_LQFP_1
UP1 UP2 = TO-247_Regulator_10
X1 X2 = Xtal_12MHz
F1 = FUSE
J5 = HEADER_4_1
J10 = DC_JACK
J23 = HEADER_4_2
J24 = HEADER_4_4
J26 = HEADER_4_5
J27 = HEADER_4_3
J29 = HEADER_36
J30 = HEADER_32
J31 = HEADER_4_6
R72 = R_1K_3
R73 = R_1K
R74 = R_1K_1
R76 = R_1K_2
U7 = 74VHC1G08_1
V1 = LM7805CT_4_v2
V2 = LM7805CT_4

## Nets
3.3V_1: CP1.1 JPR1.1 UP1.2(OUT) UP1.4(OUT)
3.3V_2: CP2.1 JPR2.1 UP2.2(OUT) UP2.4(OUT)
5V_1: JPR1.3 PD1.2 UP1.3(IN)
5V_2: JPR2.3 PD2.2 UP2.3(IN)
15V_IR_1: C70.2 C71.2 C72.2 D17.1 D18.1 D19.1 J19.11 U12.1(VCC) U13.1(VCC) U14.1(VCC)
15V_IR_2: C52.2 C53.2 C54.2 D14.1 D15.1 D16.1 J17.11 U5.1(VCC) U6.1(VCC) U11.1(VCC)
+3.3V: C20.1 C39.1 L1.7(VDD) U7.5
+5V: C3.1 C4.1 C18.1 C34.2 C36.1 C42.2 C60.1 C62.1 J12.1 J20.9 JP4.1 JP7.1 JP9.2 LED1.1 LED2.1 R9.1 R10.1 R24.1 R25.1 R66.2 R67.2 R79.1 R80.1 R81.1 R85.1 R86.2 R87.2 R88.2 R89.2 R90.2 R98.1 R99.1 R100.2 R131.1 R141.2 R151.1 R152.1 R153.1 R158.2 TP22.1(TP) U1.8 U2.8 U7.1 U7.3 U8.1(5V) U9.1(5V) U10.1(5V) V1.1(out)
+5V_IR_1: J19.9
+5V_IR_2: J17.9
+15V: C25.1 C55.1 C58.1 C59.1 J20.11 J21.2 R135.2 TP32.1(TP) V1.3(in)
AVSS_1: L3.1 U3.43(AVSS)
AVSS_2: L6.1 U4.43(AVSS)
GND: C1.2 C2.2 C3.2 C4.2 C6.2 C7.2 C8.2 C9.2 C10.2 C14.2 C15.2 C16.2 C17.2 C18.2 C20.2 C21.2 C22.1 C23.2 C24.2 C25.2 C27.1 C28.1(GND) C28.4(GND) C28.15(GND) C28.23(GND) C28.24(GND) C29.2 C30.2 C31.2 C32.2 C33.2 C34.1 C35.42(GND) C35.50(GND) C35.76(GND) C36.2 C39.2 C40.2 C41.2 C42.1 C55.2 C56.2 C57.2 C58.2 C59.2 C60.2 C61.2 C62.2 C63.2 C64.2 C65.2 C69.2 C76.2 J10.2(NA) J10.3(DC-) J11.1 J11.2 J12.2 J13.1 J13.2 J14.1 J14.2 J20.8 JP2.3 JP3.10 JP4.3 JP9.3 L1.3(CSB) L1.K R14.2 R16.2 R17.2 R19.1 R34.2 R38.2 R52.2 R62.2 R68.2 R69.2 R78.1 R104.1 R105.1 R109.1 R110.1 R114.1 R115.1 R123.2 R124.2 SW1.1(A1) SW1.2(A2) SW1.3(A3) SW1.4(A4) SW2.2 SW3.2 SW4.2 TP23.1(TP) U1.4 U2.4 U7.2 U8.2(GND) U8.9(GND) U8.10(GND) U9.2(GND) U10.4(GND) V1.2(GND) V1.4(GND)
GND_1: C5.2 C11.2 C12.2 C13.2 C19.2 C26.2 CB1.2 CP1.2 J15.5(GND) JP1.9 JP5.4 JP8.5 L2.1 L3.2 SW5.3(A3) U3.16(VSS) U3.61(VSS1) U3.63(PVSS) UP1.1(GND)
GND_2: C44.2 C45.2 C46.2 C47.2 C48.2 C443.2 CB2.2 CP2.2 J16.5(GND) JP11.9 JP12.4 JP13.5 L5.1 L6.2 SW6.3(A3) U4.16(VSS) U4.61(VSS1) U4.63(PVSS) UP2.1(GND)
GND_IR_1: C70.1 C71.1 C72.1 J19.8 U12.4(COM) U13.4(COM) U14.4(COM)
GND_IR_2: C52.1 C53.1 C54.1 J17.8 U5.4(COM) U6.4(COM) U11.4(COM)
VCC_1: C5.1 D5.1 JP8.1 JPR1.2 L4.2 R26.1 RP1.2(R1) RP1.4(R2) RP1.6(R3) RP1.8(R4) RRSET1.1 RTCK1.1 RTDA1.1 U3.15(VDD) U3.62(VDD1)
VCC_2: C443.1 D11.1 JP13.1 JPR2.2 L7.2 R45.1 RP2.2(R1) RP2.4(R2) RP2.6(R3) RP2.8(R4) RRSET2.1 RTCK2.1 RTDA4.1 U4.15(VDD) U4.62(VDD1)
VCC_connect: D5.2 JP1.1
VCC_connect (page 05-Nu-Link-ME V3.0): D11.2 JP11.1
Vin: C21.1 C22.2 C76.1 F1.2 J20.12 J21.1 J28.1 J29.1 J29.2 J29.3 J29.4 J29.5 J29.6 J29.7 J29.8 J29.9 J29.10 J29.11 J29.12 J29.13 J29.14 J29.15 J29.16 J29.17 J29.18 J29.19 J29.20 J29.21 J29.22 J29.23 J29.24 J29.25 J29.26 J29.27 J29.28 J29.29 J29.30 J29.31 J29.32 J29.33 J29.34 J29.35 J29.36 Q1.2 Q3.2 Q5.2 R77.2 TP47.1(TP) TP52.1(TP) TP54.1(TP)
VIN_IR_1: J19.12
VIN_IR_2: J17.12
12M_I: C26.1 U3.59(XT1_In) X1.1
12M_I (page 05-Nu-Link-ME V3.0): C48.1 U4.59(XT1_In) X2.1
12M_O: R40.1 U3.58(XT1_Out)
12M_O (page 05-Nu-Link-ME V3.0): R46.1 U4.58(XT1_Out)
Bemf_O: C35.70(Bemf_O) R144.2 R145.2 R146.2
Bemf_U: C35.44(Bemf_U) R138.1 R142.2 R146.1
Bemf_V: C35.46(Bemf_V) R133.2 R137.1 R145.1
Bemf_W: C35.48(Bemf_W) R134.1 R143.2 R144.1
DAC_CS: C28.12(DAC_CS) U8.4(CS)
DAC_SCK: C28.16(DAC_CK) U8.6(CK)
DAC_SDO: C28.14(DAC_DO) U8.5(DO)
DC_EX: J9.1 J9.2 J10.1(DC+) J67.2 R378.1 TP21.1(TP)
DC_in: F1.1 J67.1 R378.2
DCV: C27.2 C35.47(DCV) R77.1 R78.2
DIP1: C28.9(DIP1) R87.1 SW1.8(B1)
DIP2: C28.7(DIP2) R86.1 SW1.7(B2)
DIP3: C28.5(DIP3) R88.1 SW1.6(B3)
DIP4: C28.3(DIP4) R89.1 SW1.5(B4)
DISP_RS: C28.32(DISP_RS) R92.2
DISP_RST: C28.34(DISP_RST) R91.2 R131.2 SW4.1
DISP_SCK: C28.30(DISP_SCK) R93.2 R129.1
DISP_SDO: C28.28(DISP_SDO) R95.2 R130.1
DM: J15.2(DM) JP5.2 R41.2
DM (page 05-Nu-Link-ME V3.0): J16.2(DM) JP12.2 R47.2
DP: J15.3(DP) JP5.3 R43.2
DP (page 05-Nu-Link-ME V3.0): J16.3(DP) JP12.3 R50.2
EX_I_OC: C6.1 C35.51(EX_I_OC) JP10.2 R27.2 R28.1
EX_I_Shunt: C35.45(EX_I_Shunt) C69.1 JP10.1 R27.1 R157.2
EX_I_Sum: C7.1 C35.43(EX_I_SUM) JP10.3 R28.2
EX_IRSum: C28.40(IRSUM) R126.4
G5V: J20.10 JP7.3
G5V_NC: J19.10
G5V_NC (page 07-IR2101): J17.10
GREEN: BUSY1.2 U3.13(CTS1/PB7)
GREEN (page 05-Nu-Link-ME V3.0): BUSY2.2 U4.13(CTS1/PB7)
H-U: J12.3 R81.2 R82.1
H-V: J12.4 R80.2 R84.1
H-W: J12.5 R79.2 R83.1
Hall_U: C29.1 C35.52(Hall_U) R82.2
Hall_V: C31.1 C35.54(Hall_V) R84.2
Hall_W: C30.1 C35.56(Hall_W) R83.2
HO_U: 19.3 D6.2 R44.1 TP10.1(TP)
HO_U_IR: J22.3 U14.7(HO)
HO_U_IR (page 07-IR2101): J18.3 U11.7(HO)
HO_V: 19.7 D3.2 R33.1 TP5.1(TP)
HO_V_IR: J22.7 U13.7(HO)
HO_V_IR (page 07-IR2101): J18.7 U6.7(HO)
HO_W: 19.11 D1.2 R8.1 TP1.1(TP)
HO_W_IR: J22.11 U12.7(HO)
HO_W_IR (page 07-IR2101): J18.11 U5.7(HO)
I_U: C35.55(I_U) R7.2
I_V: C35.57(I_V) R30.2
I_W: C35.41(I_W) R6.2
ICE_AVDD_1: L4.1 U3.52(AVDD)
ICE_AVDD_2: L7.1 U4.52(AVDD)
ICE_CLK: C28.37(ICE_CLK) JP3.6 R160.2
ICE_CLK (page 04-Nu-Link-ME V3.0): JP8.3 U3.42(ICE_CLK)
ICE_CLK (page 05-Nu-Link-ME V3.0): JP13.3 U4.42(ICE_CLK)
ICE_DAT: C28.35(ICE_DAT) JP3.4 R159.2
ICE_DAT (page 04-Nu-Link-ME V3.0): JP8.2 U3.41(ICE_DAT)
ICE_DAT (page 05-Nu-Link-ME V3.0): JP13.2 U4.41(ICE_DAT)
ICE_RST: C28.39(ICE_RST) C40.1 JP3.8 R94.2
ICE_RST (page 04-Nu-Link-ME V3.0): C12.1 JP8.4 R26.2 U3.60(/RESET)
ICE_RST (page 05-Nu-Link-ME V3.0): C45.1 JP13.4 R45.2 U4.60(/RESET)
ICE_RX: JP1.10 SW5.2(A2)
ICE_RX (page 05-Nu-Link-ME V3.0): JP11.10 SW6.2(A2)
ICE_TX: JP1.8 SW5.1(A1)
ICE_TX (page 05-Nu-Link-ME V3.0): JP11.8 SW6.1(A1)
ICECLK: JP1.5 RTCK1.2 U3.35(PC9/SPCLK1)
ICECLK (page 05-Nu-Link-ME V3.0): JP11.5 RTCK2.2 U4.35(PC9/SPCLK1)
ICEDAT: JP1.3 RTDA1.2 RTDA2.2 RTDA3.2
ICEDAT (page 05-Nu-Link-ME V3.0): JP11.3 RTDA4.2 RTDA5.2 RTDA6.2
ICELED: ICE1.2 U3.10(RX1/PB4)
ICELED (page 05-Nu-Link-ME V3.0): ICE2.2 U4.10(RX1/PB4)
ICERST: JP1.7 RRSET1.2 U3.36(PC8/SS10)
ICERST (page 05-Nu-Link-ME V3.0): JP11.7 RRSET2.2 U4.36(PC8/SS10)
IRSum: J30.1 J30.2 J30.3 J30.4 J30.5 J30.6 J30.7 J30.8 J30.9 J30.10 J30.11 J30.12 J30.13 J30.14 J30.15 J30.16 J30.17 J30.18 J30.19 J30.20 J30.21 J30.22 J30.23 J30.24 J30.25 J30.26 J30.27 J30.28 J30.29 J30.30 J30.31 J30.32 R1.1 R3.1 R22.1 R63.2 R64.2 R65.2 R68.1 R69.1 R126.2 R126.3 TP41.1(TP)
IRU: Q6.3 R12.1 R58.2 R65.1 TP42.1(TP) TP61.1(TP)
IRU+: R9.2 R12.2 R16.1 R119.2
IRV: Q4.3 R32.1 R39.2 R64.1 TP43.1(TP) TP59.1(TP)
IRV+: R24.2 R32.2 R34.1 R120.2
IRW: Q2.3 R11.1 R21.2 R63.1 TP44.1(TP) TP49.1(TP)
IRW+: R10.2 R11.2 R14.1 R125.2
ISPLED: ICP1.2 U3.11(TX1/PB5)
ISPLED (page 05-Nu-Link-ME V3.0): ICP2.2 U4.11(TX1/PB5)
Iu+: C35.65(Iu+) R119.3
Iv+: C35.61(Iv+) R120.3
Iw+: C35.66(Iw_+) R125.3
KEY1: C28.19(KEY1/DISP+SDO) R98.2 R130.2 SW2.1
KEY2: C28.17(KEY2/DISP_SCK) R99.2 R129.2 SW3.1
LED1: C28.29(LED1) R96.2
LED2: C28.31(LED2) R97.2
LO_U: 19.1 D7.2 R55.1 TP12.1(TP)
LO_U_IR: J22.1 U14.5(LO)
LO_U_IR (page 07-IR2101): J18.1 U11.5(LO)
LO_V: 19.5 D4.2 R37.1 TP7.1(TP)
LO_V_IR: J22.5 U13.5(LO)
LO_V_IR (page 07-IR2101): J18.5 U6.5(LO)
LO_W: 19.9 D2.2 R18.1 TP3.1(TP)
LO_W_IR: J22.9 U12.5(LO)
LO_W_IR (page 07-IR2101): J18.9 U5.5(LO)
MCU_5V: C28.25(5V) C28.26(5V) C32.1 C33.1 D12.2 JP7.2 R94.1 R159.1 R160.1
PC4_IR_NC: J19.7
PC4_IR_NC (page 07-IR2101): J17.7
QEI_A: C35.62(QEIA) C63.1 R155.2
QEI_B: C35.60(QEIB) C64.1 R156.2
QEI_Z: C35.58(IDX) C65.1 R154.2
RED: IDLE1.2 U3.12(RTS1/PB6)
RED (page 05-Nu-Link-ME V3.0): IDLE2.2 U4.12(RTS1/PB6)
RUN1: C28.21(RUN) JP2.2
RXD: SW5.8(B1) U3.21(PB0/RX0)
RXD (page 05-Nu-Link-ME V3.0): SW6.8(B1) U4.21(PB0/RX0)
SP_CMD: C28.2(SP_CMD) JP6.2
Speed: C41.1 JP4.2 JP6.1
TXD: SW5.7(B2) U3.22(PB1/TX0)
TXD (page 05-Nu-Link-ME V3.0): SW6.7(B2) U4.22(PB1/TX0)
U: 19.2 J6.1 J6.2 J7.1 J7.2 Q5.3 Q6.2 R42.2 R139.1 R149.1 TP56.1(TP) TP60.1(TP)
U_HIN: J20.6 R112.2
U_HIN_IR: J19.6 U14.2(HIN)
U_HIN_IR (page 07-IR2101): J17.6 U11.2(HIN)
U_LIN: J20.5 R113.2
U_LIN_IR: J19.5 U14.3(LIN)
U_LIN_IR (page 07-IR2101): J17.5 U11.3(LIN)
UART0_RXD: C28.20(RXD) JP3.9 R100.1 U10.2(M_RX)
UART0_TXD: C28.18(TXD) JP3.7 R158.1 U10.3(M_TX)
UH: C35.75(UH) R112.1 R114.2
UL: C35.67(UL) R113.1 R115.2
USB_D+: R43.1 U3.20(D+)
USB_D+ (page 05-Nu-Link-ME V3.0): R50.1 U4.20(D+)
USB_D-: R41.1 U3.19(D-)
USB_D- (page 05-Nu-Link-ME V3.0): R47.1 U4.19(D-)
USBVBUS_1: C11.1 J15.1(VCC) JP5.1 PD1.1 U3.17(VBUS)
USBVBUS_2: C44.1 J16.1(VCC) JP12.1 PD2.1 U4.17(VBUS)
V: 19.6 J3.1 J3.2 J4.1 J4.2 Q3.3 Q4.2 R29.2 R136.1 R148.1 TP53.1(TP) TP57.1(TP)
V_HIN: J20.4 R107.2
V_HIN_IR: J19.4 U13.2(HIN)
V_HIN_IR (page 07-IR2101): J17.4 U6.2(HIN)
V_LIN: J20.3 R108.2
V_LIN_IR: J19.3 U13.3(LIN)
V_LIN_IR (page 07-IR2101): J17.3 U6.3(LIN)
VB_U: 19.4
VB_U_IR: C68.1 J22.4 R101.2 U14.8(VB)
VB_U_IR (page 07-IR2101): C51.1 J18.4 R54.2 U11.8(VB)
VB_V: 19.8
VB_V_IR: C67.1 J22.8 R75.2 U13.8(VB)
VB_V_IR (page 07-IR2101): C50.1 J18.8 R53.2 U6.8(VB)
VB_W: 19.12
VB_W_IR: C66.1 J22.12 R60.2 U12.8(VB)
VB_W_IR (page 07-IR2101): C49.1 J18.12 R51.2 U5.8(VB)
VCOM_pin: SW5.6(B3) U3.29(PE5)
VCOM_pin (page 05-Nu-Link-ME V3.0): SW6.6(B3) U4.29(PE5)
VH: C35.77(VH) R107.1 R109.2
VL: C35.69(VL) R108.1 R110.2
VS_U_IR: J22.2 R106.2 U14.6(VS)
VS_U_IR (page 07-IR2101): J18.2 R56.2 U11.6(VS)
VS_V_IR: J22.6 R111.2 U13.6(VS)
VS_V_IR (page 07-IR2101): J18.6 R57.2 U6.6(VS)
VS_W: 19.10 J1.1 J1.2 J2.1 J2.2 Q1.3 Q2.2 R5.2 R132.1 R147.1 TP46.1(TP) TP50.1(TP)
VS_W_IR: J22.10 R116.2 U12.6(VS)
VS_W_IR (page 07-IR2101): J18.10 R59.2 U5.6(VS)
VSP: JP6.3 R128.1
W_HIN: J20.2 R102.2
W_HIN_IR: J19.2 U12.2(HIN)
W_HIN_IR (page 07-IR2101): J17.2 U5.2(HIN)
W_LIN: J20.1 R103.2
W_LIN_IR: J19.1 U12.3(LIN)
W_LIN_IR (page 07-IR2101): J17.1 U5.3(LIN)
WH: C35.79(WH) R102.1 R104.2
WL: C35.71(WL) R103.1 R105.2
N00874: BUSY1.1 RP1.7(R4)
N00882: IDLE1.1 RP1.5(R3)
N00906: ICE1.1 RP1.1(R1)
N00938: ICP1.1 RP1.3(R2)
N07793: C19.1 R40.2 X1.2
N26617: C67.2 R111.1
N16812063: C13.1 U3.14(LDO)
N16812255: CB1.1 U3.18(VDD33)
N16812376: RTDA3.1 U3.33(PC11/SDO10)
N17861502: RTDA2.1 U3.34(PC10/SDI10)
N18771284: J15.6(SHIELD) J15.7(SHIELD) J15.8(SHIELD) J15.9(SHIELD) L2.2
N21306144: L1.A R90.1
N21306564: C38.2 L1.6(VSS)
N21306567: C38.1 L1.8(VOUT)
N21306589: C37.1 L1.9(C1+)
N21306592: C37.2 L1.10(C1-)
N21306844: L1.1(RST) R91.1
N21306849: L1.2(RS) R92.1
N21306854: L1.4(SCL) R93.1
N21306859: L1.5(SI) R95.1
N21312922: R153.2 R155.1 U9.3(QEI_A)
N21312925: R151.2 R156.1 U9.4(QEI_B)
N21316522: LED2.2 R97.1
N21316568: LED1.2 R96.1
N21333093: D10.2 R72.1 R74.1
N21333097: C23.1 J8.1 R72.2 R73.1 R74.2 R76.1
N21333100: C24.1 J8.2 R73.2 R76.2 TP20.1(TP) V2.3(in)
N21469236: D6.1 Q5.1 R42.1 R44.2 TP11.1(TP) TP55.1(TP)
N21469303: D7.1 Q6.1 R55.2 R58.1 TP13.1(TP) TP62.1(TP)
N21469387: C15.1 R48.2 R49.1 R52.1
N21469405: C14.1 R49.2 R142.1
N21469502: D1.1 Q1.1 R5.1 R8.2 TP2.1(TP) TP45.1(TP)
N21469508: D2.1 Q2.1 R18.2 R21.1 TP4.1(TP) TP48.1(TP)
N21469651: C1.1 R13.2 R15.1 R17.1
N21469653: C2.1 R15.2 R143.1
N21469744: D4.1 Q4.1 R37.2 R39.1 TP8.1(TP) TP58.1(TP)
N21469760: D3.1 Q3.1 R29.1 R33.2 TP6.1(TP) TP51.1(TP)
N21469885: C9.1 R35.2 R36.1 R38.1
N21469895: C10.1 R36.2 R133.1
N21477922: R4.2 R7.1 U1.7
N21477926: R3.2 R4.1 U1.6
N21486409: R20.2 R157.1 U2.1
N21486417: R19.2 R20.1 U2.2
N21496651: R23.2 R30.1 U1.1
N21496659: R22.2 R23.1 U1.2
N21496775: R2.2 R6.1 U2.7
N21496779: R1.2 R2.1 U2.6
N21515329: R121.1 R135.1 V2.2(Out)
N21520272: R119.1 U1.5
N21522649: R120.1 U1.3
N21541785: D17.2 R60.1
N21541937: D18.2 R75.1
N21542078: D19.2 R101.1
N21571980: C56.1 R121.2 R122.2 R124.1 V2.1(ADJ)
N21572284: R122.1 R123.1
N21572787: R125.1 U2.5
N21573171: C8.1 R25.2 R31.2 U2.3
N21586266: D12.1 JP3.2
N21608705: D8.1 R66.1 R70.2
N21608715: D9.1 R67.1 R71.2
N21608717: C16.1 R70.1 R137.2
N21608733: C17.1 R71.1 R134.2
N21627161: D9.2 R132.2
N21630045: D8.2 R136.2
N21630681: D13.2 R139.2
N21630699: C61.1 R138.2 R140.1
N21630733: D13.1 R140.2 R141.1
N21632011: R31.1 R126.1
N21633894: R13.1 R147.2
N21633951: R48.1 R149.2
N21633972: R35.1 R148.2
N21637973: D10.1 J28.2
N21641585: JP2.1 R85.2
N21645956: R152.2 R154.1 U9.5(QEI_Z)
N21686032: C57.1 JP9.1 R61.2
N21686038: R61.1 R62.1 R128.2
N21798932: IDLE2.1 RP2.5(R3)
N21798947: CB2.1 U4.18(VDD33)
N21798948: ICP2.1 RP2.3(R2)
N21798953: BUSY2.1 RP2.7(R4)
N21798957: RTDA6.1 U4.33(PC11/SDO10)
N21798959: ICE2.1 RP2.1(R1)
N21798991: C46.1 U4.14(LDO)
N21798994: C47.1 R46.2 X2.2
N21799026: RTDA5.1 U4.34(PC10/SDI10)
N21799050: J16.6(SHIELD) J16.7(SHIELD) J16.8(SHIELD) J16.9(SHIELD) L5.2
N21800561: D14.2 R51.1
N21800577: D15.2 R53.1
N21800589: D16.2 R54.1
N21800635: C51.2 R56.1
N21800636: C50.2 R57.1
N21800637: C49.2 R59.1
N21805409: C68.2 R106.1
N21805561: C66.2 R116.1

Not connected (* = marked no-connect by the designer): C28 6(-)* 8(-)* 10(-)* 11(-)* 13(-)* 22(-)* 27(-)* 33(-)* 36(-)* 38(-)*; C35 49(-)* 53(-)* 59(-)* 63(-)* 64(-)* 68(-)* 72(-)* 73(-)* 74(-)* 78(-)* 80(-)*; J5 1 2 3 4; J15 4(NC)*; J16 4(NC)*; J20 7*; J23 1 2 3 4; J24 1 2 3 4; J25 1 2 3 4; J26 1 2 3 4; J27 1 2 3 4; J31 1 2 3 4; J67 3*; JP1 2* 4* 6*; JP3 1* 3* 5*; JP11 2* 4* 6*; SW5 4(A4)* 5(B4)*; SW6 4(A4)* 5(B4)*; TP9 1(TP)*; TP24 1(TP)*; TP25 1(TP)*; TP26 1(TP)*; TP27 1(TP)*; TP28 1(TP)*; TP29 1(TP)*; TP30 1(TP)*; TP31 1(TP)*; TP39 1(TP)*; TP40 1(TP)*; U3 1(INT0/PB14)* 2(CPO1/PB13)* 3(CPO0/PB12)* 4(X32I)* 5(X32O)* 6(I2C1SCL/PA11)* 7(I2C1SDA/PA10)* 8(I2C0SCL/PA9)* 9(I2C0SDA/PA8)* 23(PB2/RTS0)* 24(PB3/CTS0)* 25(PC3/SDO00)* 26(PC2/SDI00)* 27(PC1/SPCLK0)* 28(PC0/SS00)* 30(PB11/TM3)* 31(PB10/SS01/TM2)* 32(PB9/SS11/TM1)* 37(PA15/PWM3)* 38(PA14/PWM2)* 39(PA13/PWM1)* 40(PA12/PWM0)* 44(PA0/ADC0)* 45(PA1/ADC1)* 46(PA2/ADC2)* 47(PA3/ADC3)* 48(PA4/ADC4)* 49(ADC/PA5)* 50(ADC6/PA6)* 51(ADC7/PA7)* 53(CPN0/PC7)* 54(CPP0/PC6)* 55(CPN1/PC15)* 56(CPP1/PC14)* 57(INT1/PB15)* 64(STADC/TM0/PB8)*; U4 1(INT0/PB14)* 2(CPO1/PB13)* 3(CPO0/PB12)* 4(X32I)* 5(X32O)* 6(I2C1SCL/PA11)* 7(I2C1SDA/PA10)* 8(I2C0SCL/PA9)* 9(I2C0SDA/PA8)* 23(PB2/RTS0)* 24(PB3/CTS0)* 25(PC3/SDO00)* 26(PC2/SDI00)* 27(PC1/SPCLK0)* 28(PC0/SS00)* 30(PB11/TM3)* 31(PB10/SS01/TM2)* 32(PB9/SS11/TM1)* 37(PA15/PWM3)* 38(PA14/PWM2)* 39(PA13/PWM1)* 40(PA12/PWM0)* 44(PA0/ADC0)* 45(PA1/ADC1)* 46(PA2/ADC2)* 47(PA3/ADC3)* 48(PA4/ADC4)* 49(ADC/PA5)* 50(ADC6/PA6)* 51(ADC7/PA7)* 53(CPN0/PC7)* 54(CPP0/PC6)* 55(CPN1/PC15)* 56(CPP1/PC14)* 57(INT1/PB15)* 64(STADC/TM0/PB8)*; U7 4*; U8 3(VRE)* 7(O4)* 8(O3)* 11(O2)* 12(O1)*

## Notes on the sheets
sheet 1
- Connect point
- Connect point
- Connect point
sheet 2
- Vin
- GND
- Low Voltage Power_VIN= 24V ~ 48V or VIN= 15V
- Hall Sensor Power
sheet 3
- 5V
  GND
  U
  V
  W
- DIP Switch
- Screw
  Holes
sheet 4
- ICE_USB
- ICE_Status
- 12M Oscillators
- RESET
- VCOM switch
- DEBUG
- power switch
- SWD connect
sheet 5
- ICE_USB
- ICE_Status
- 12M Oscillators
- RESET
- VCOM switch
- DEBUG
- power switch
- SWD connect
